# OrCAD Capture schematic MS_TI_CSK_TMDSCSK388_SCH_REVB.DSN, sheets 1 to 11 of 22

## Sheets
1 22.HARDWARE SCHEMATICS: title: HARDWARE SCHEMATICS; rev: B; note: MS_TI_CSK_TMDSCSK388_SCH_REVB
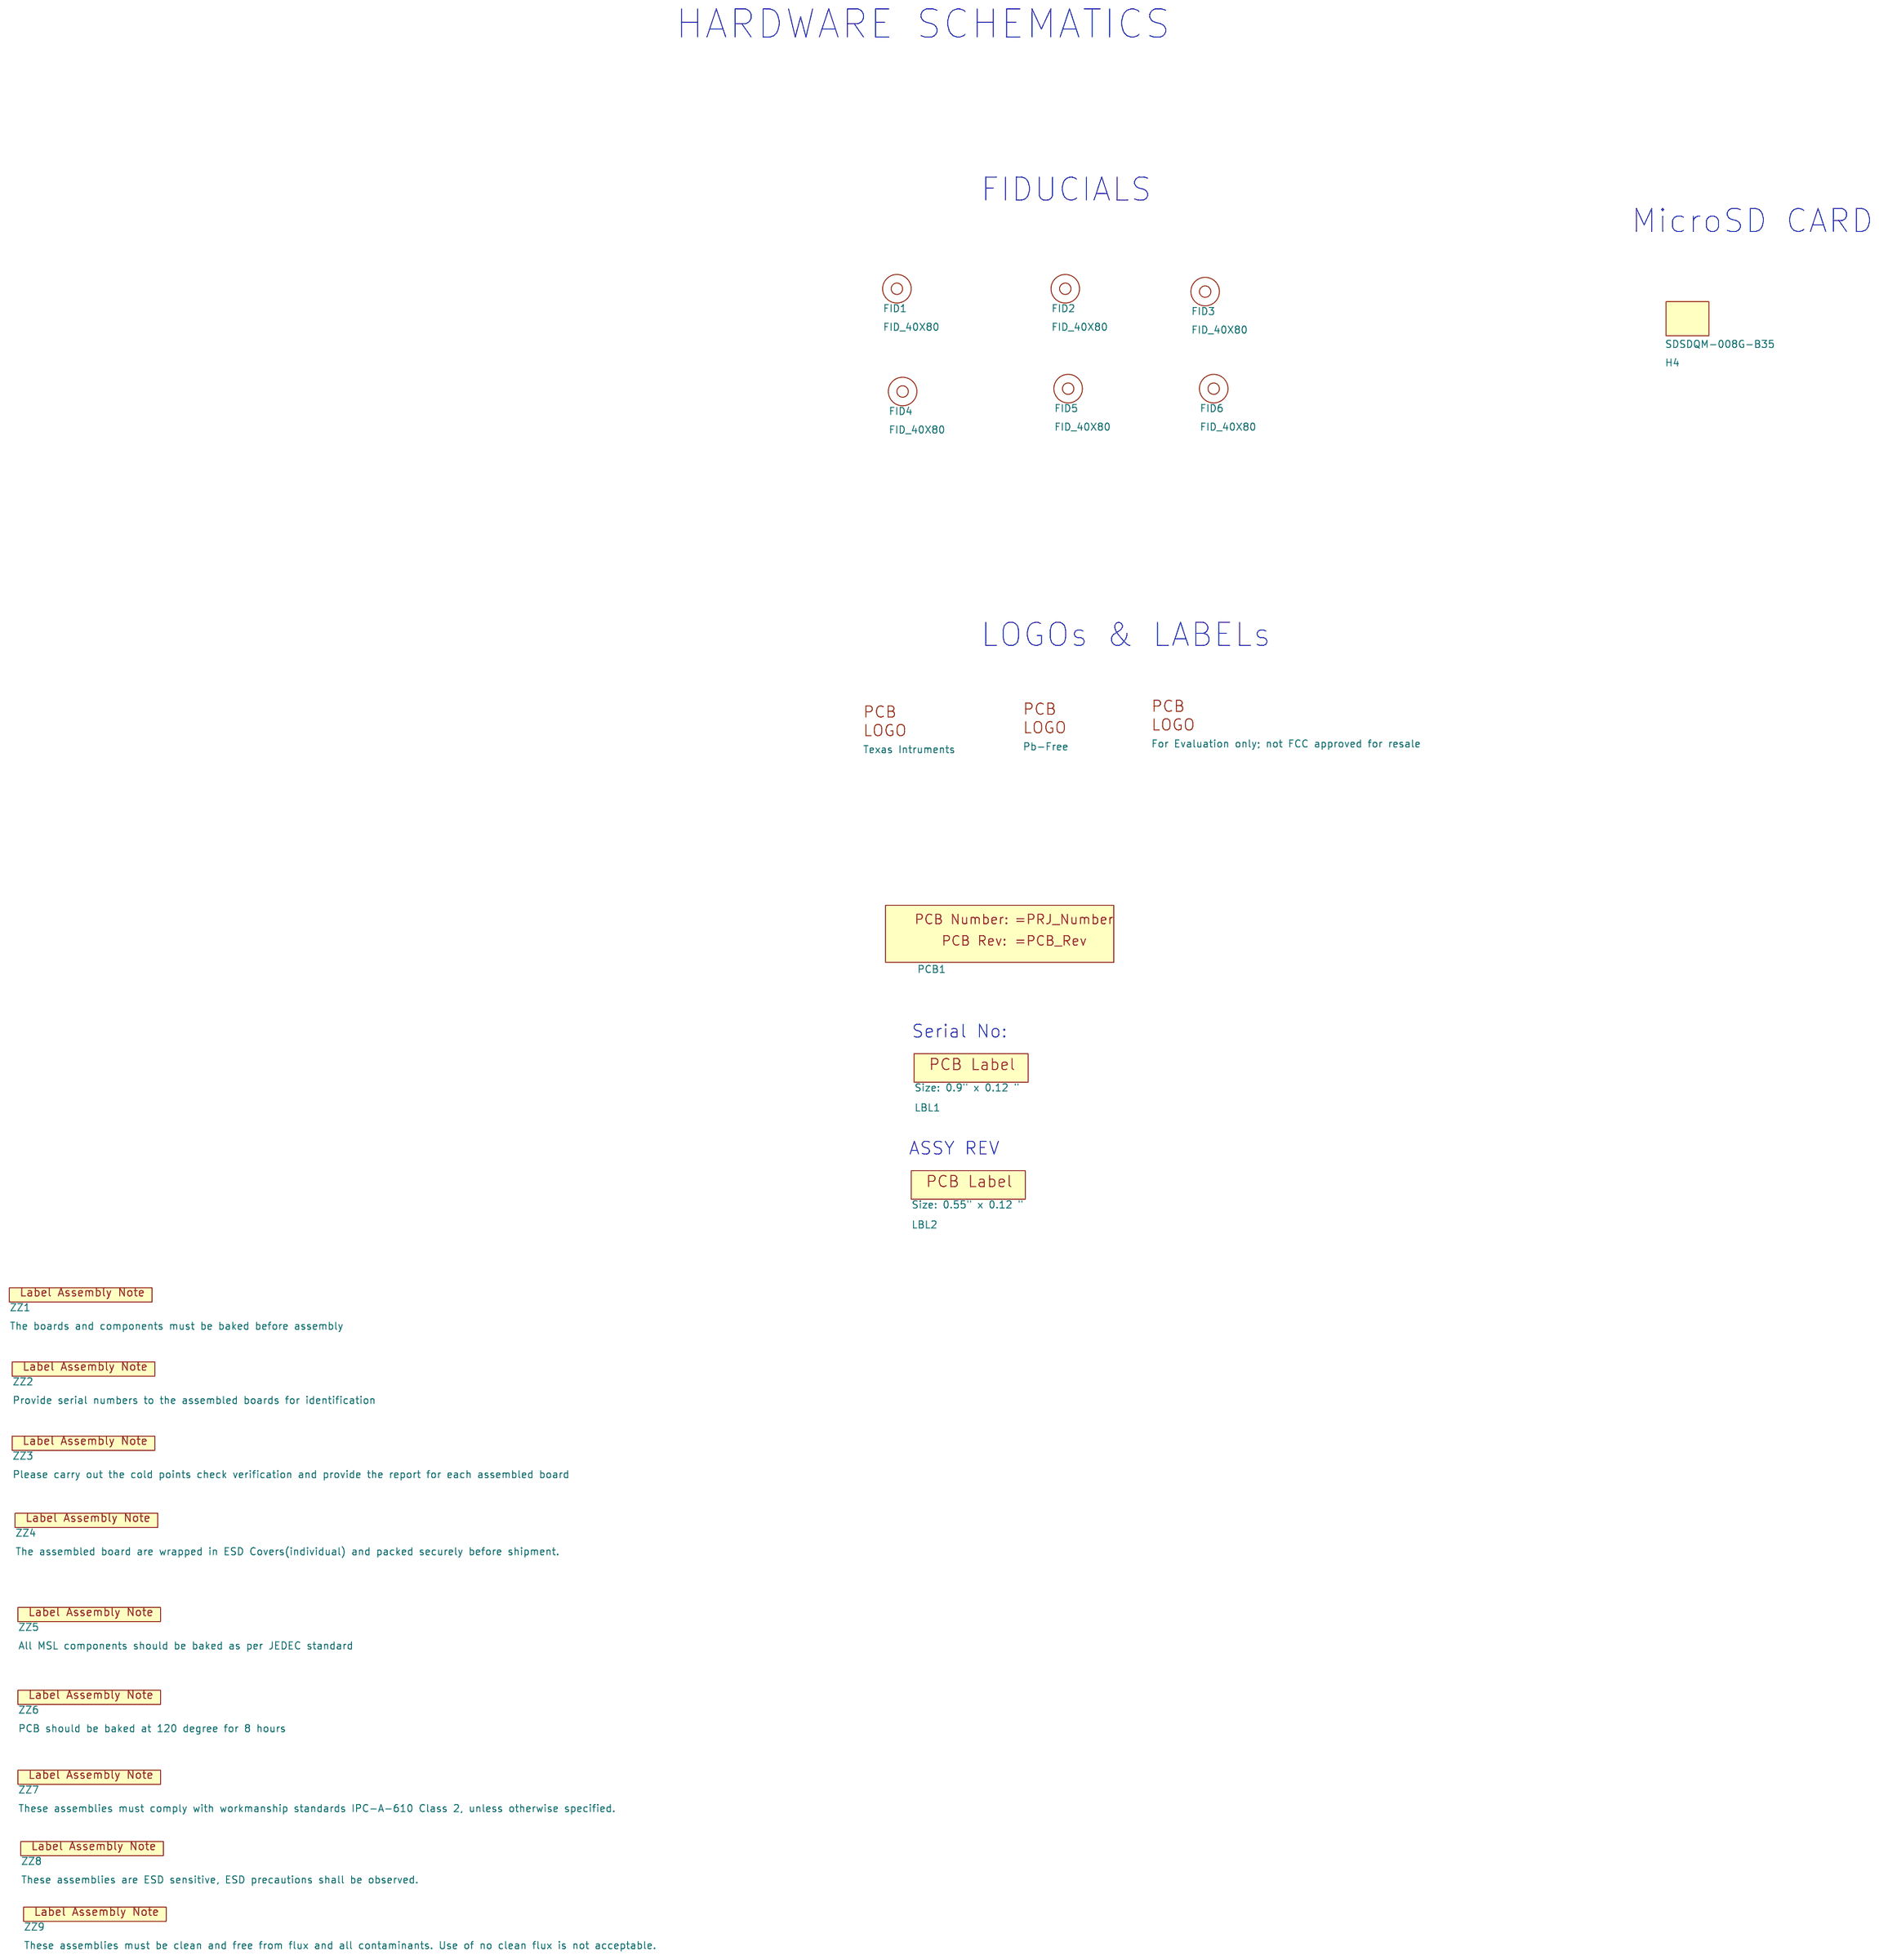
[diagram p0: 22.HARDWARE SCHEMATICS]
2 06.POWER CALCULATION: title: POWER CALCULATION
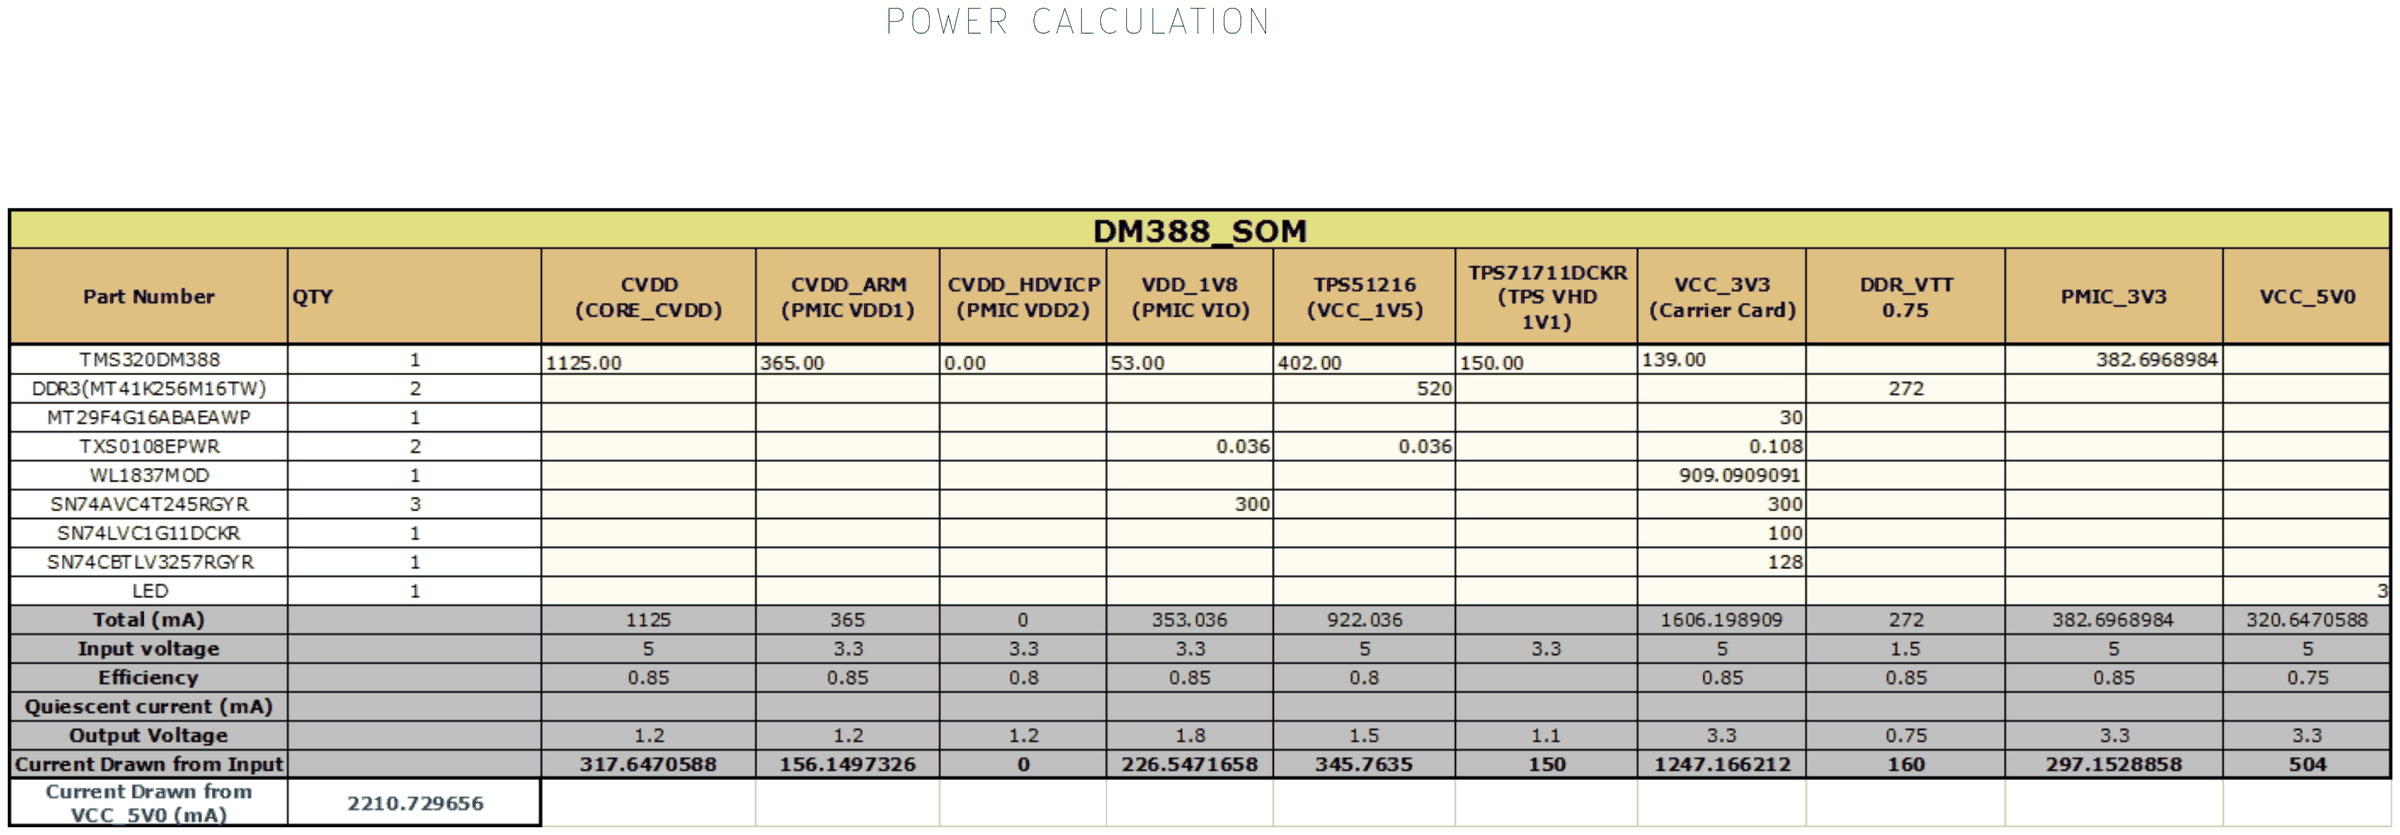
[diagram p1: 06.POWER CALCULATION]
3 05.POWER UP SEQUENCE: title: POWER UP SEQUENCE
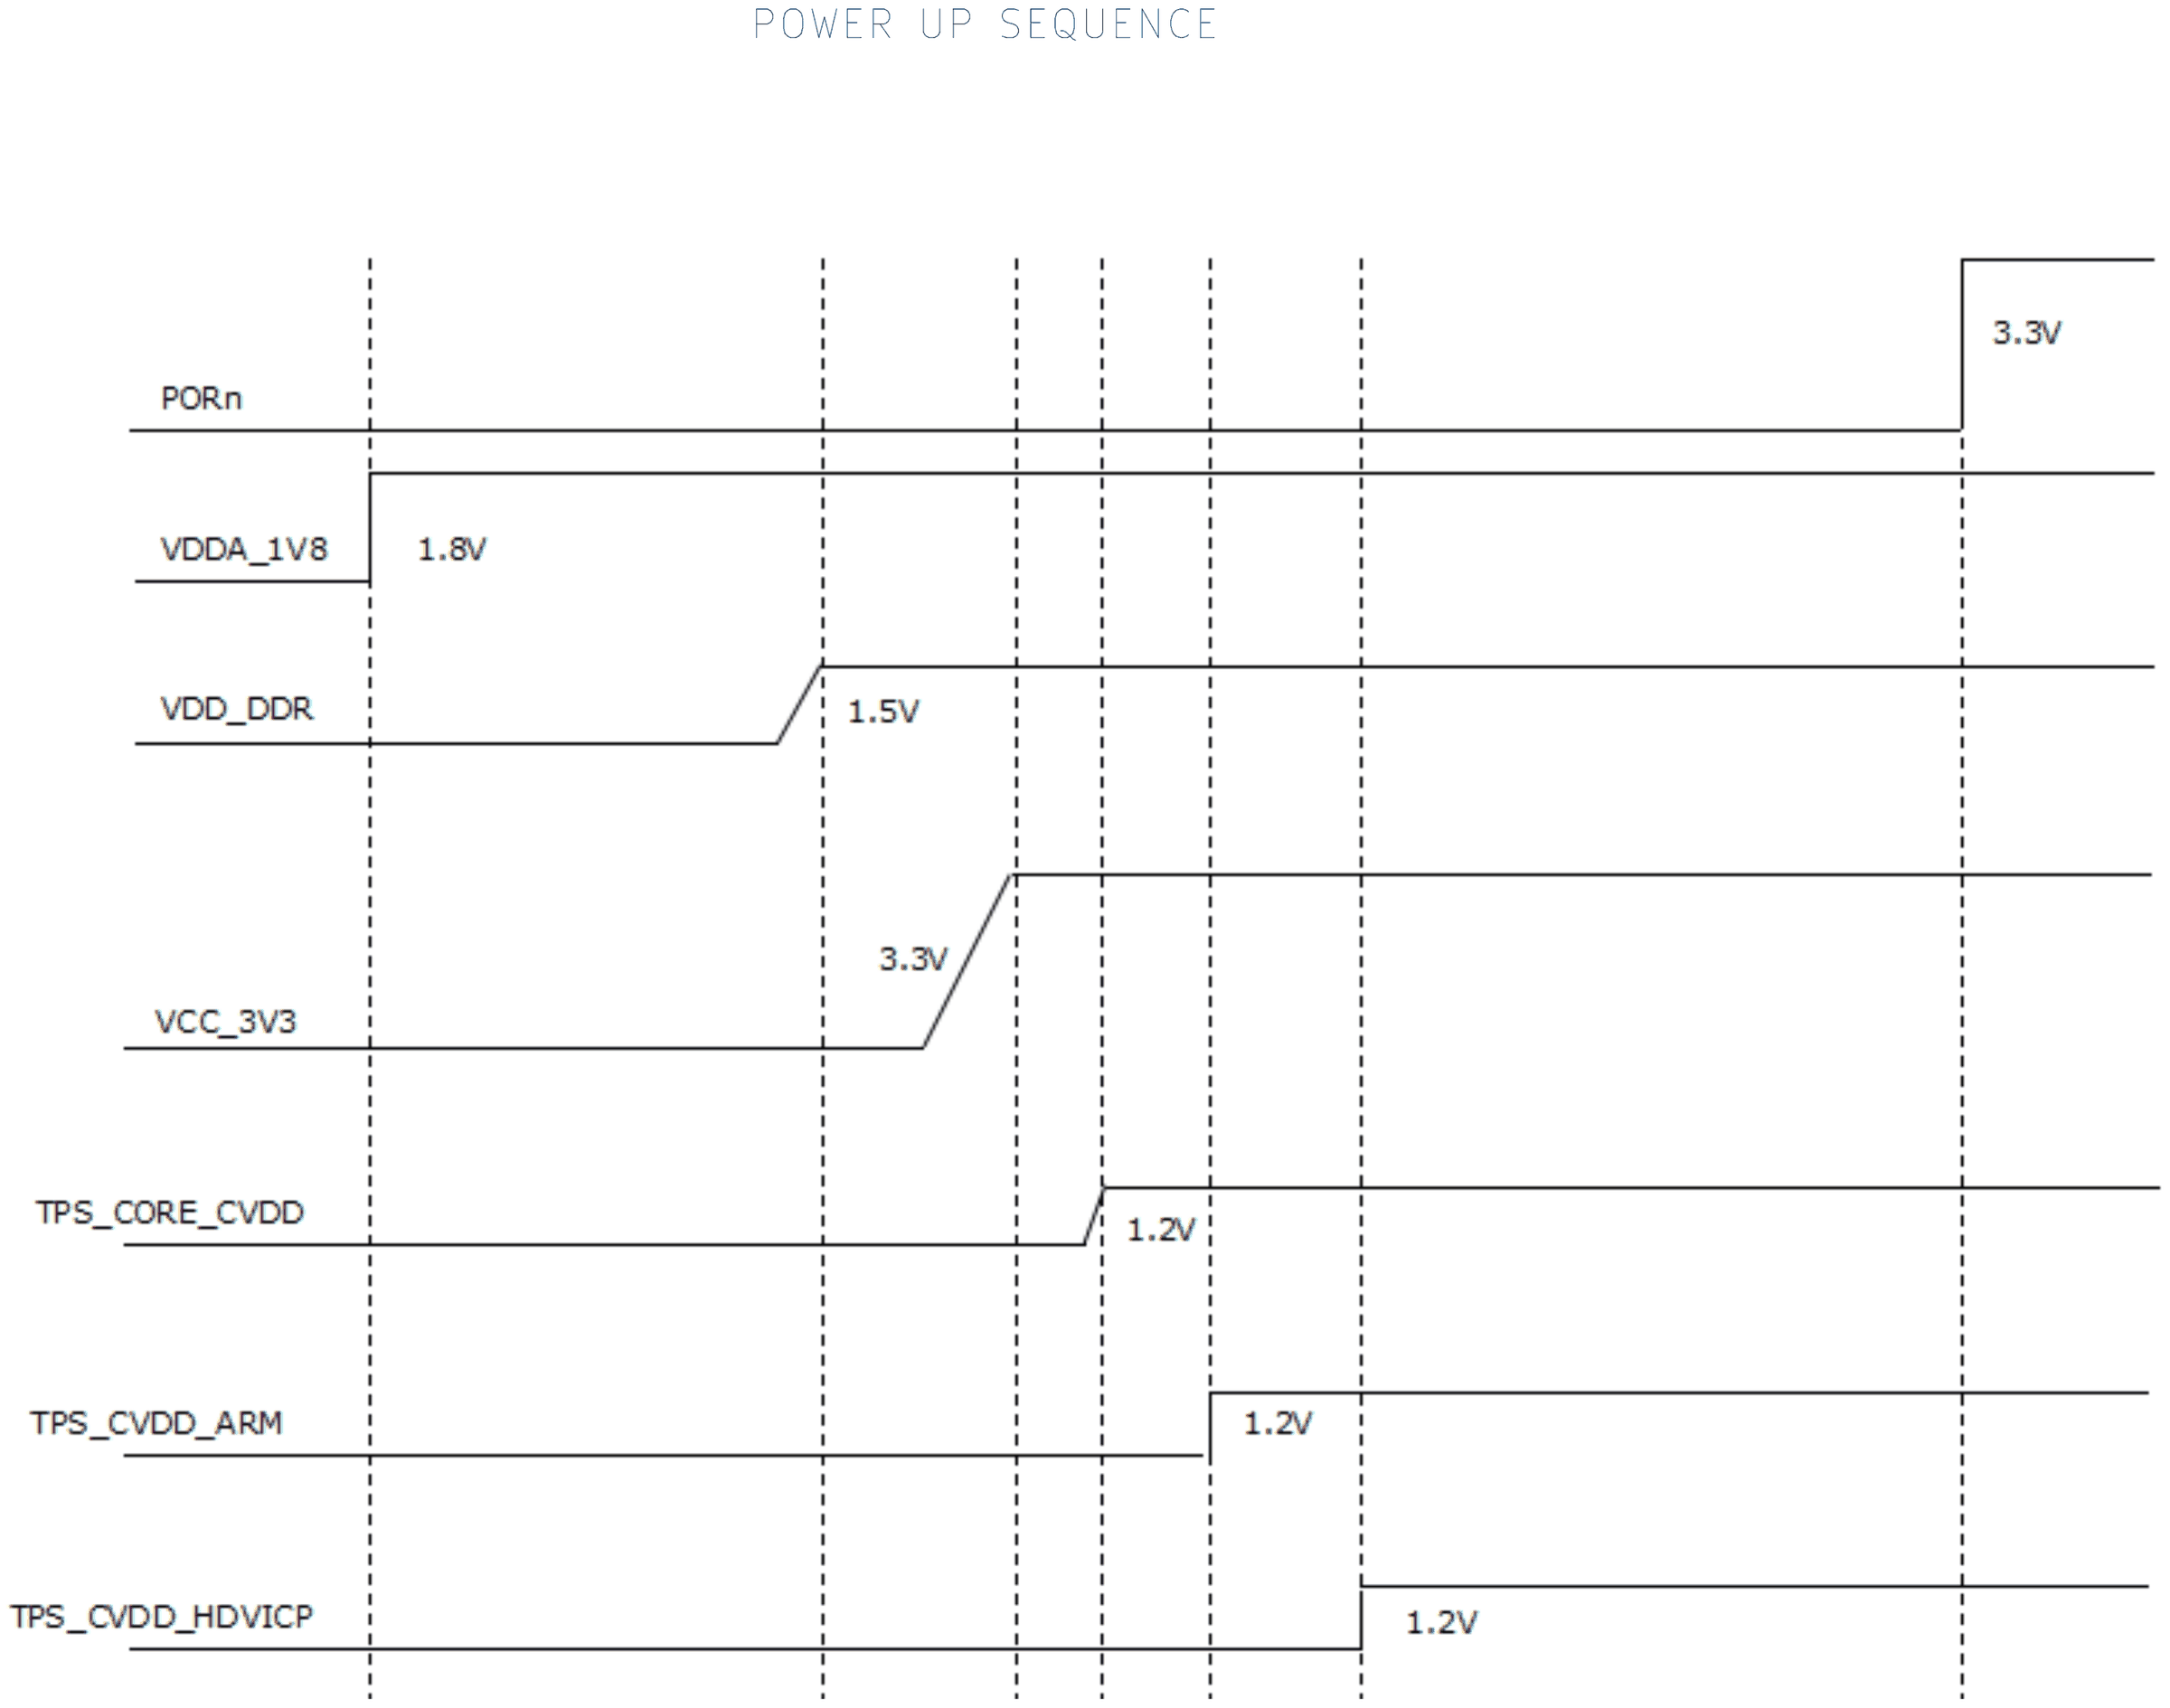
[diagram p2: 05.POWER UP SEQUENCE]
4 07.GPIO & I2C ADDRESS TABLE: title: GPIO & I2C ADDRESS TABLE
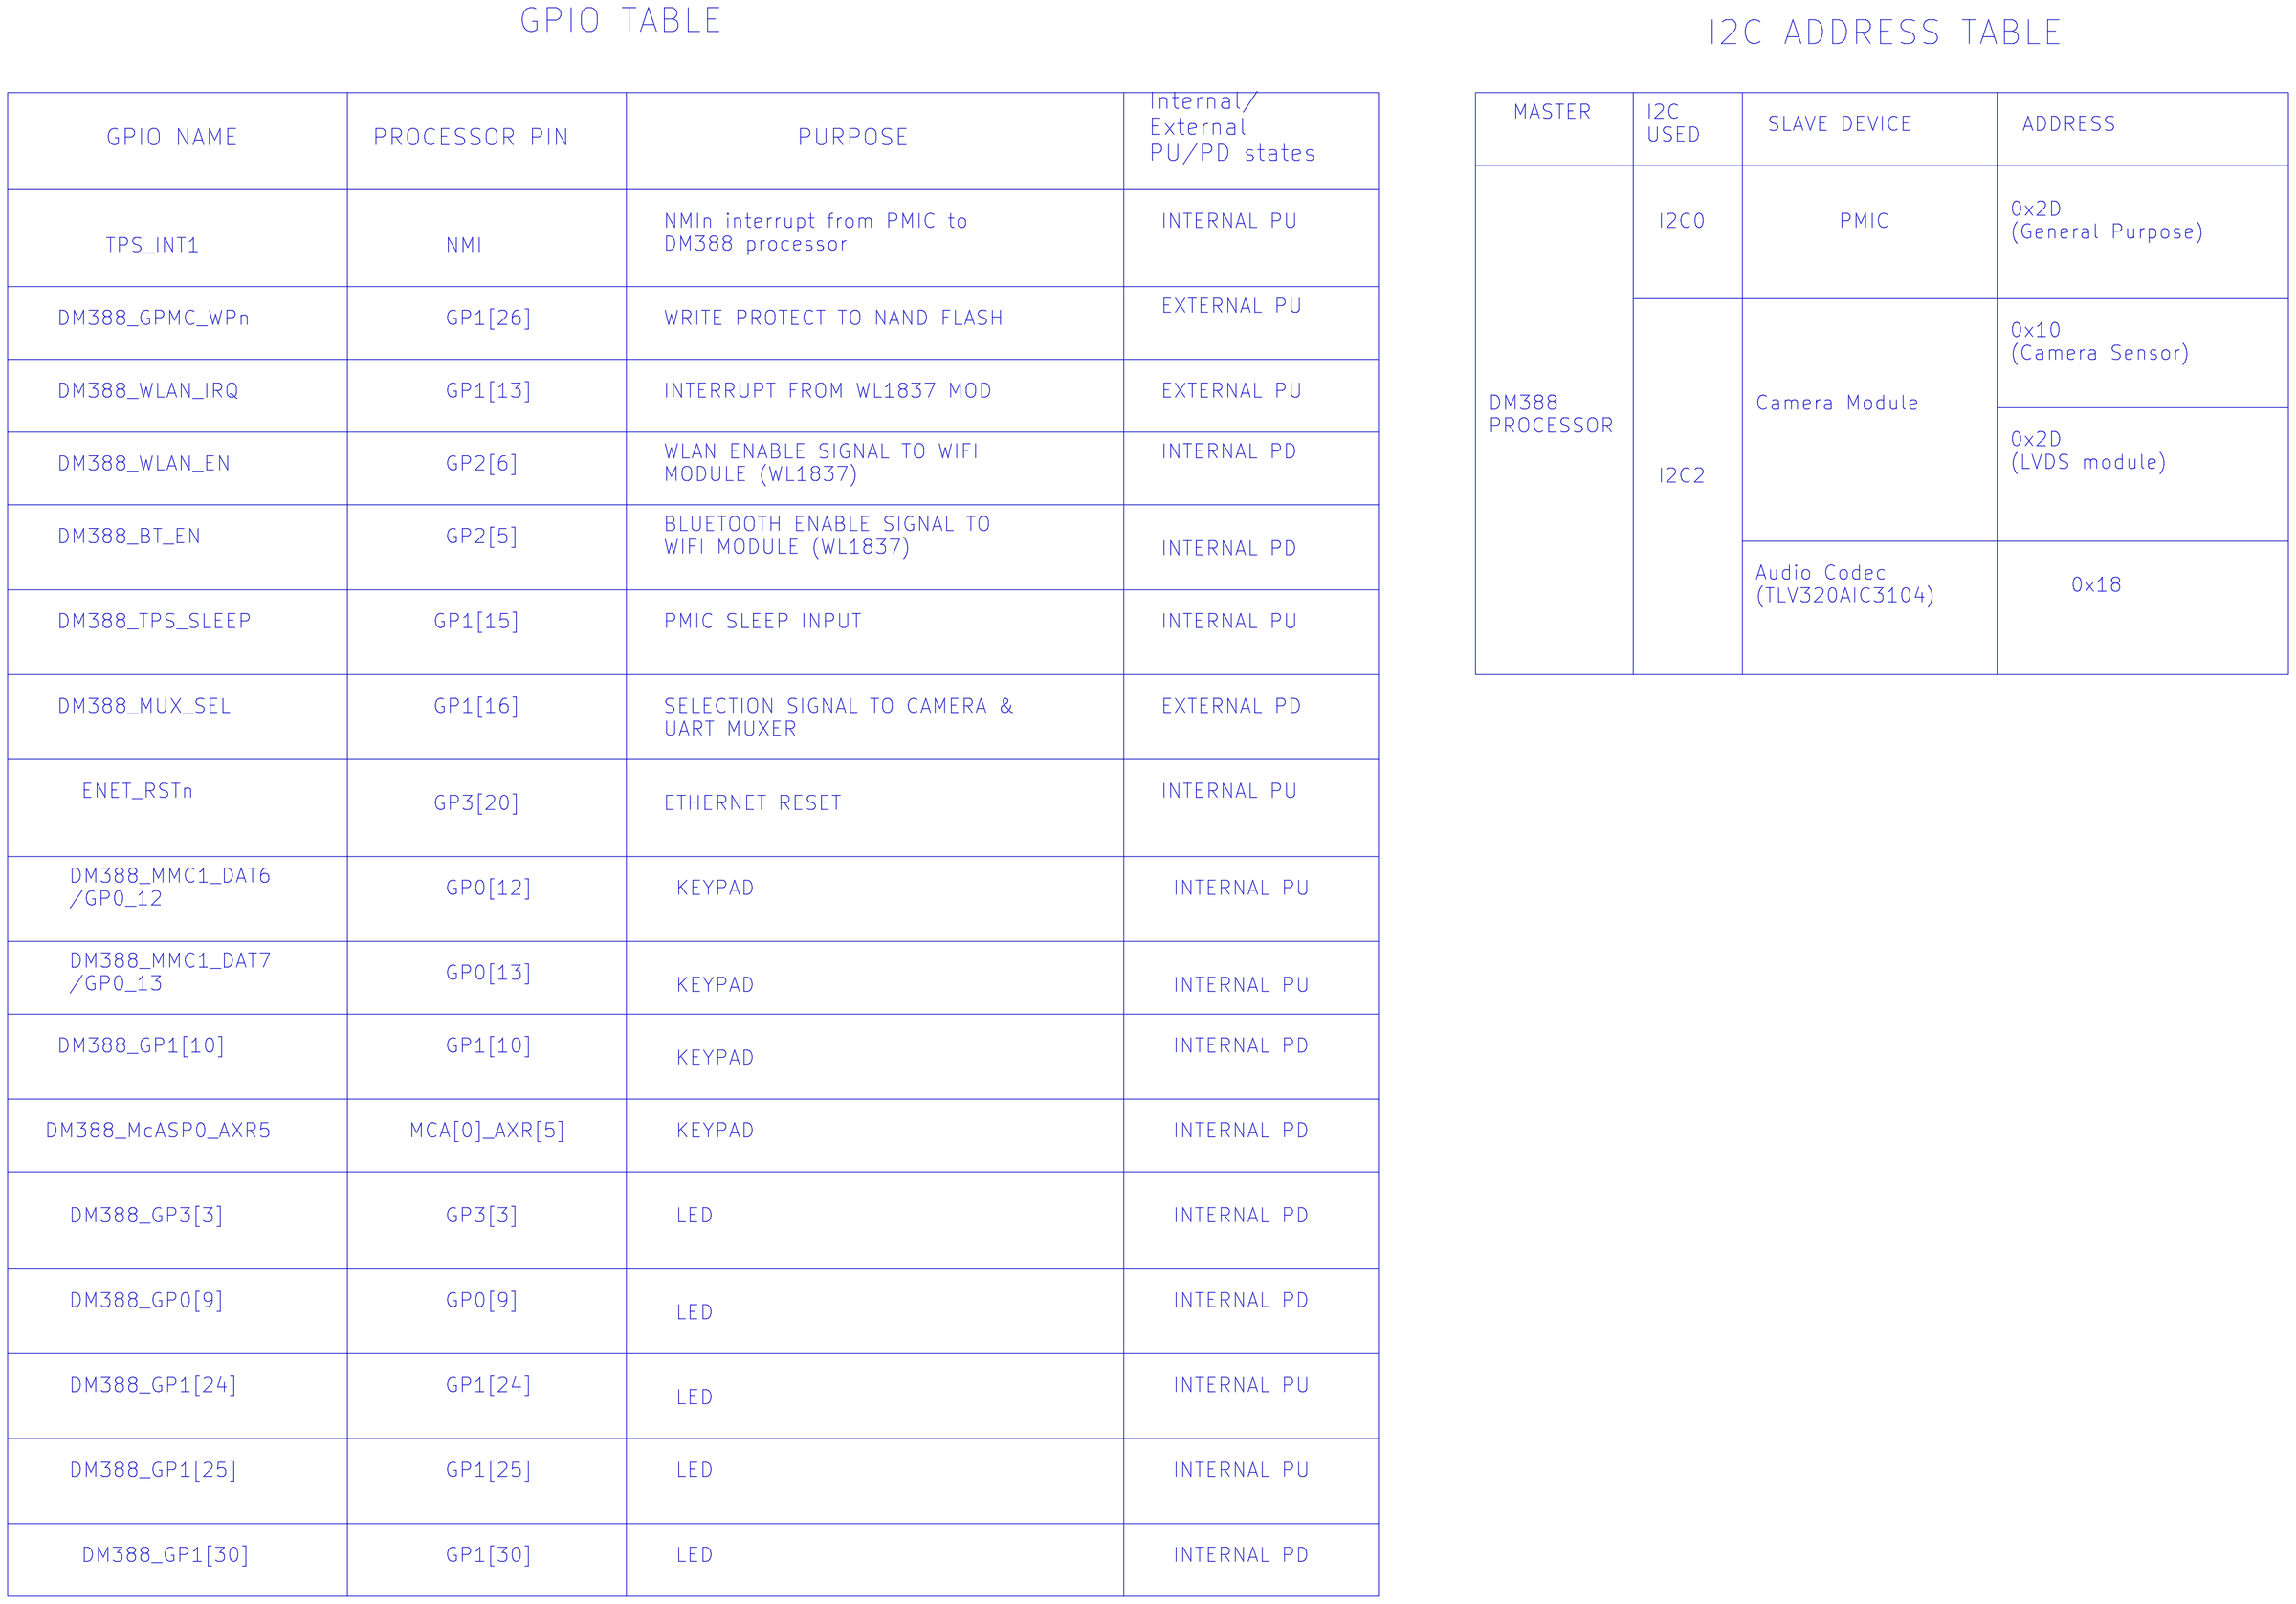
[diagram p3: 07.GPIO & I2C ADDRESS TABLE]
5 01.TABLE OF CONTENTS: title: TABLE OF CONTENTS
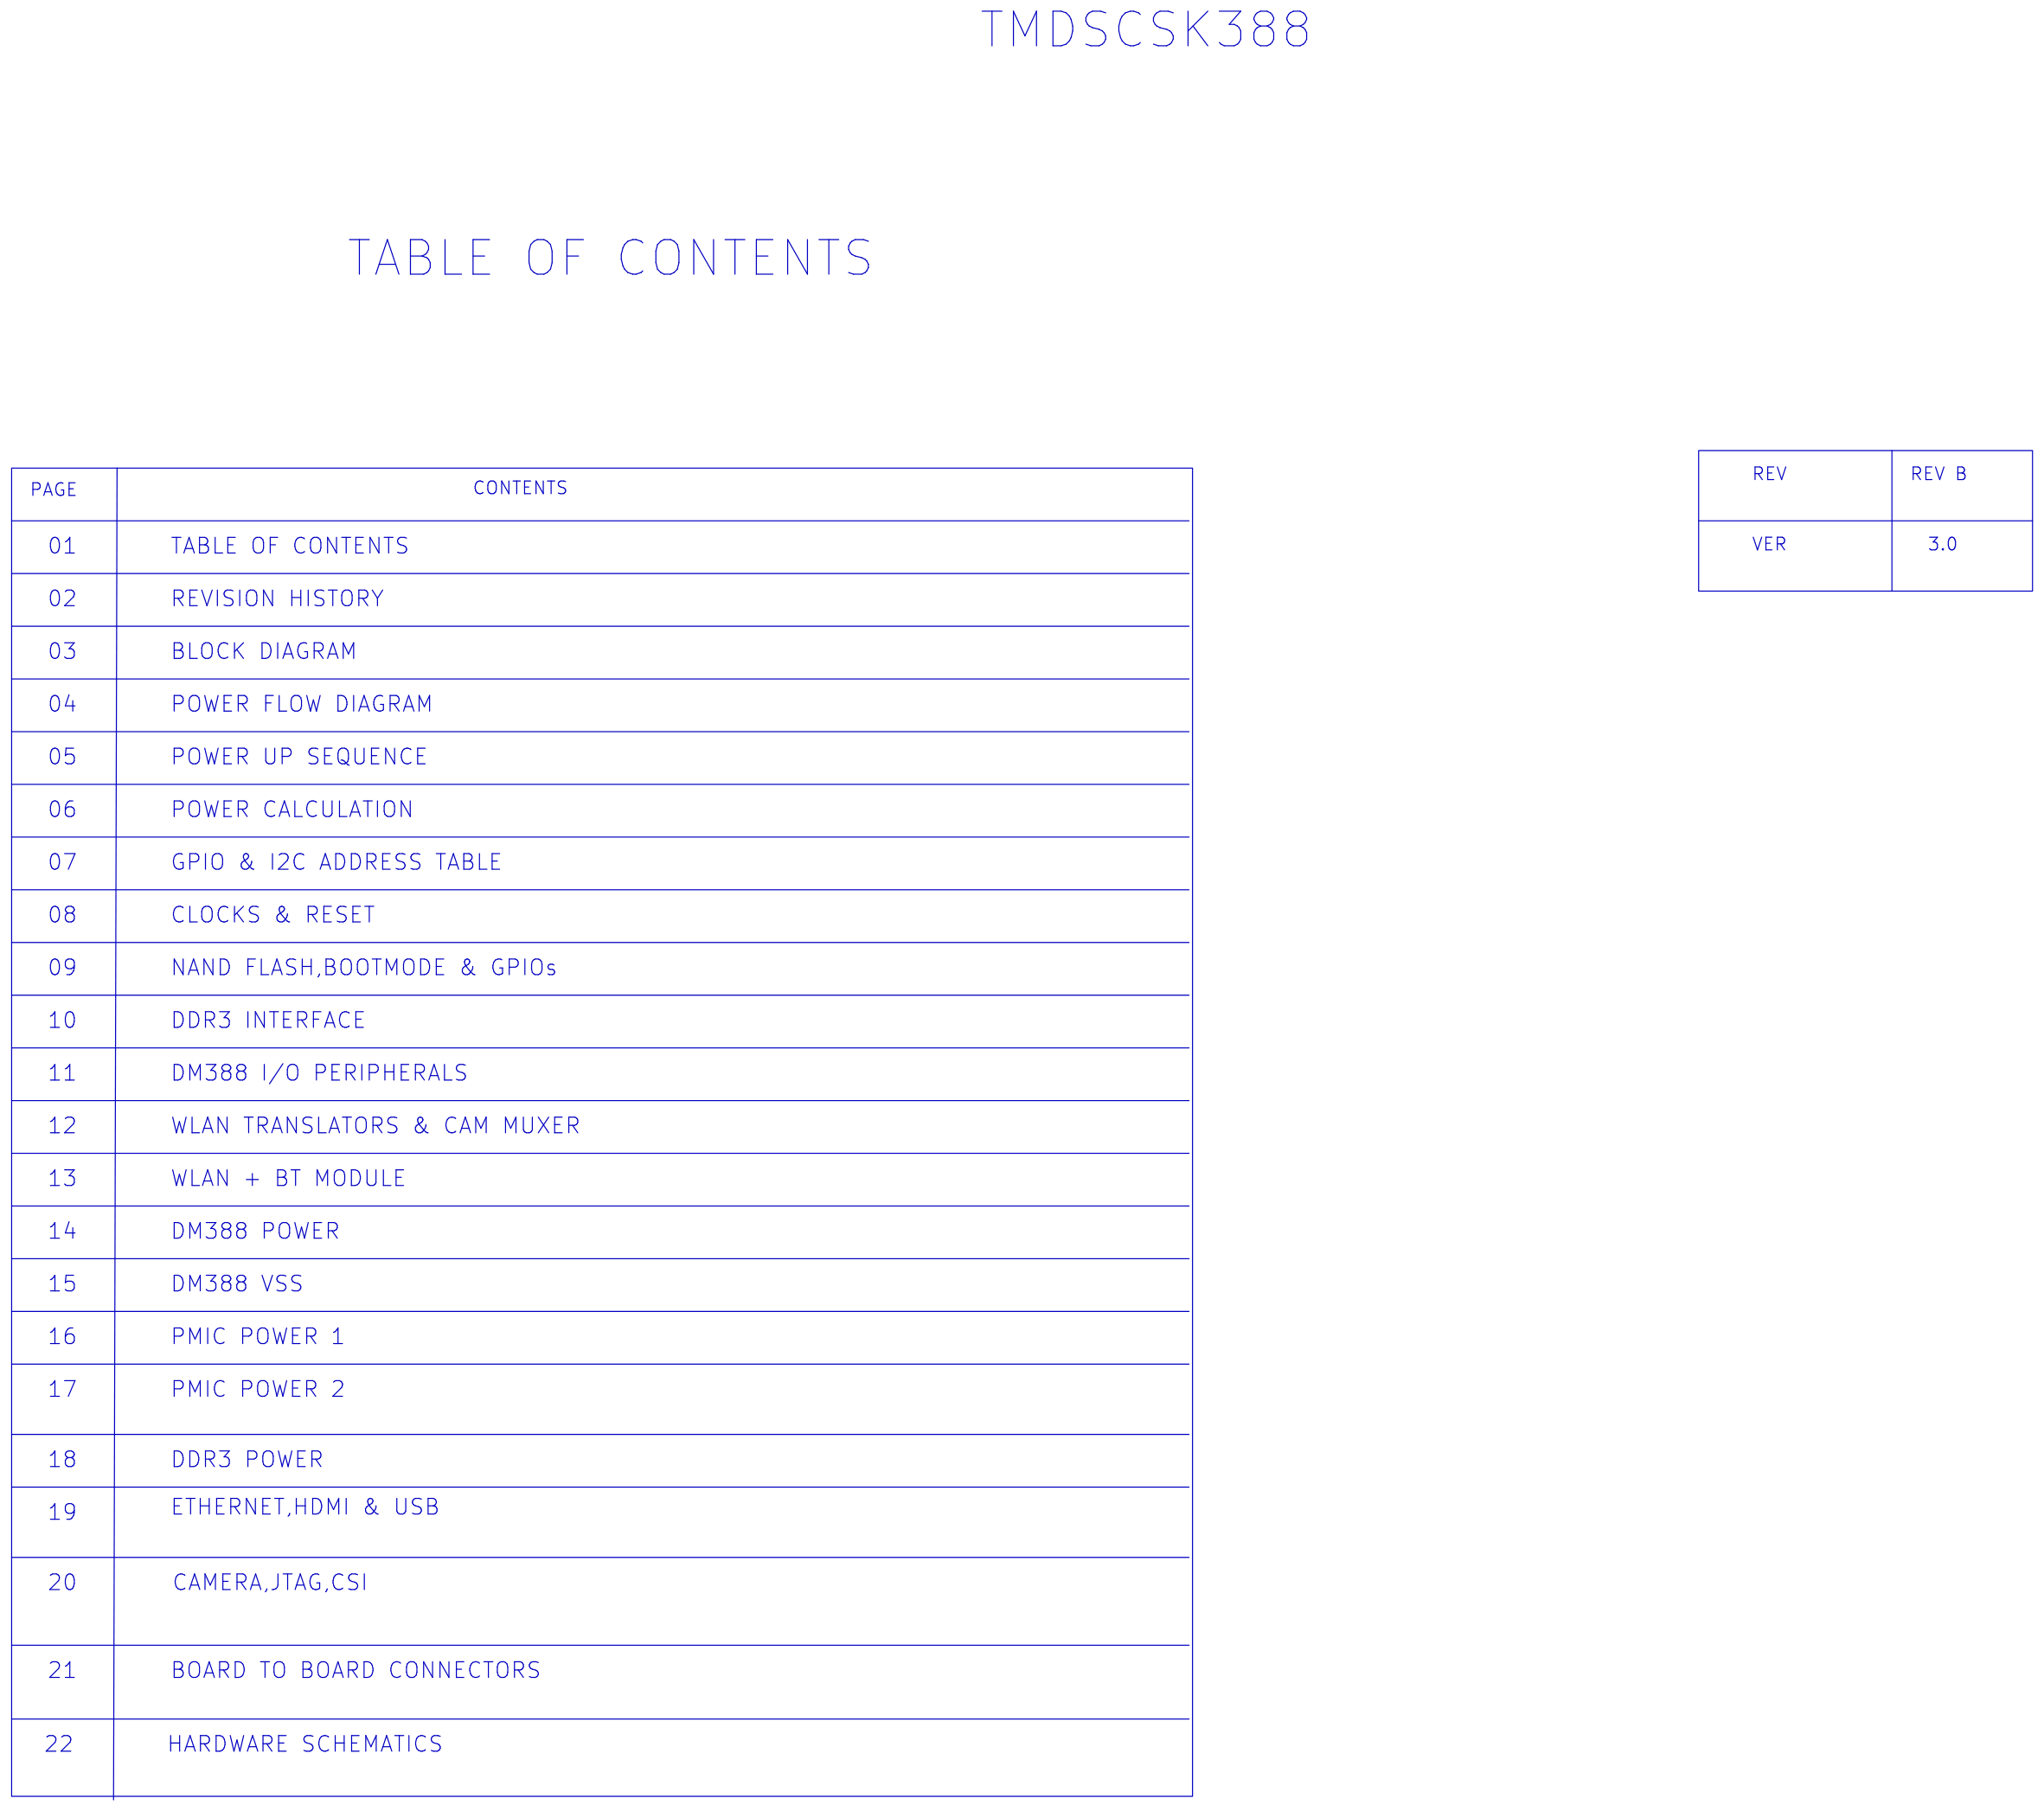
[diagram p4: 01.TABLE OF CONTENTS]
6 02. REVISION HISTORY: title: REVISION HISTORY
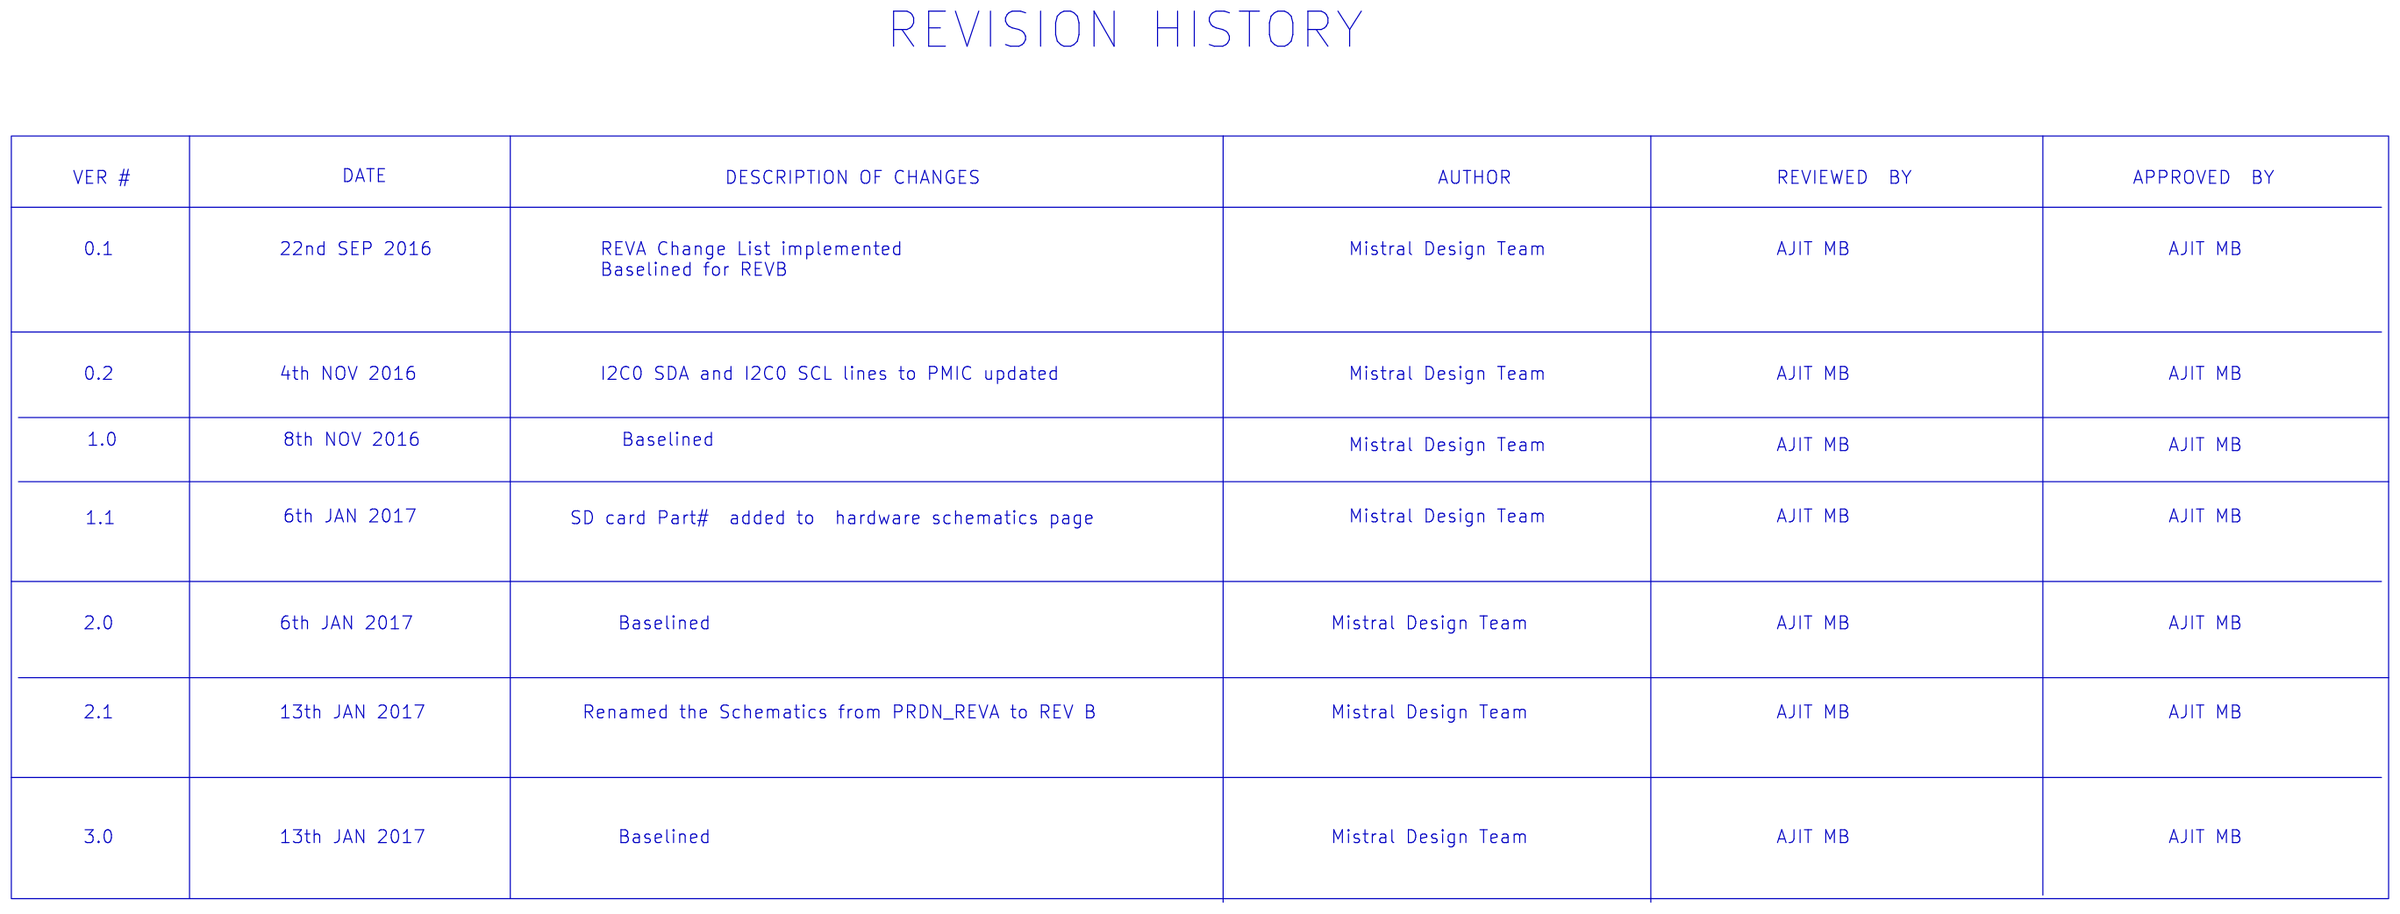
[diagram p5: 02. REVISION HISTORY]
7 03. BLOCK DIAGRAM: title: BLOCK DIAGRAM
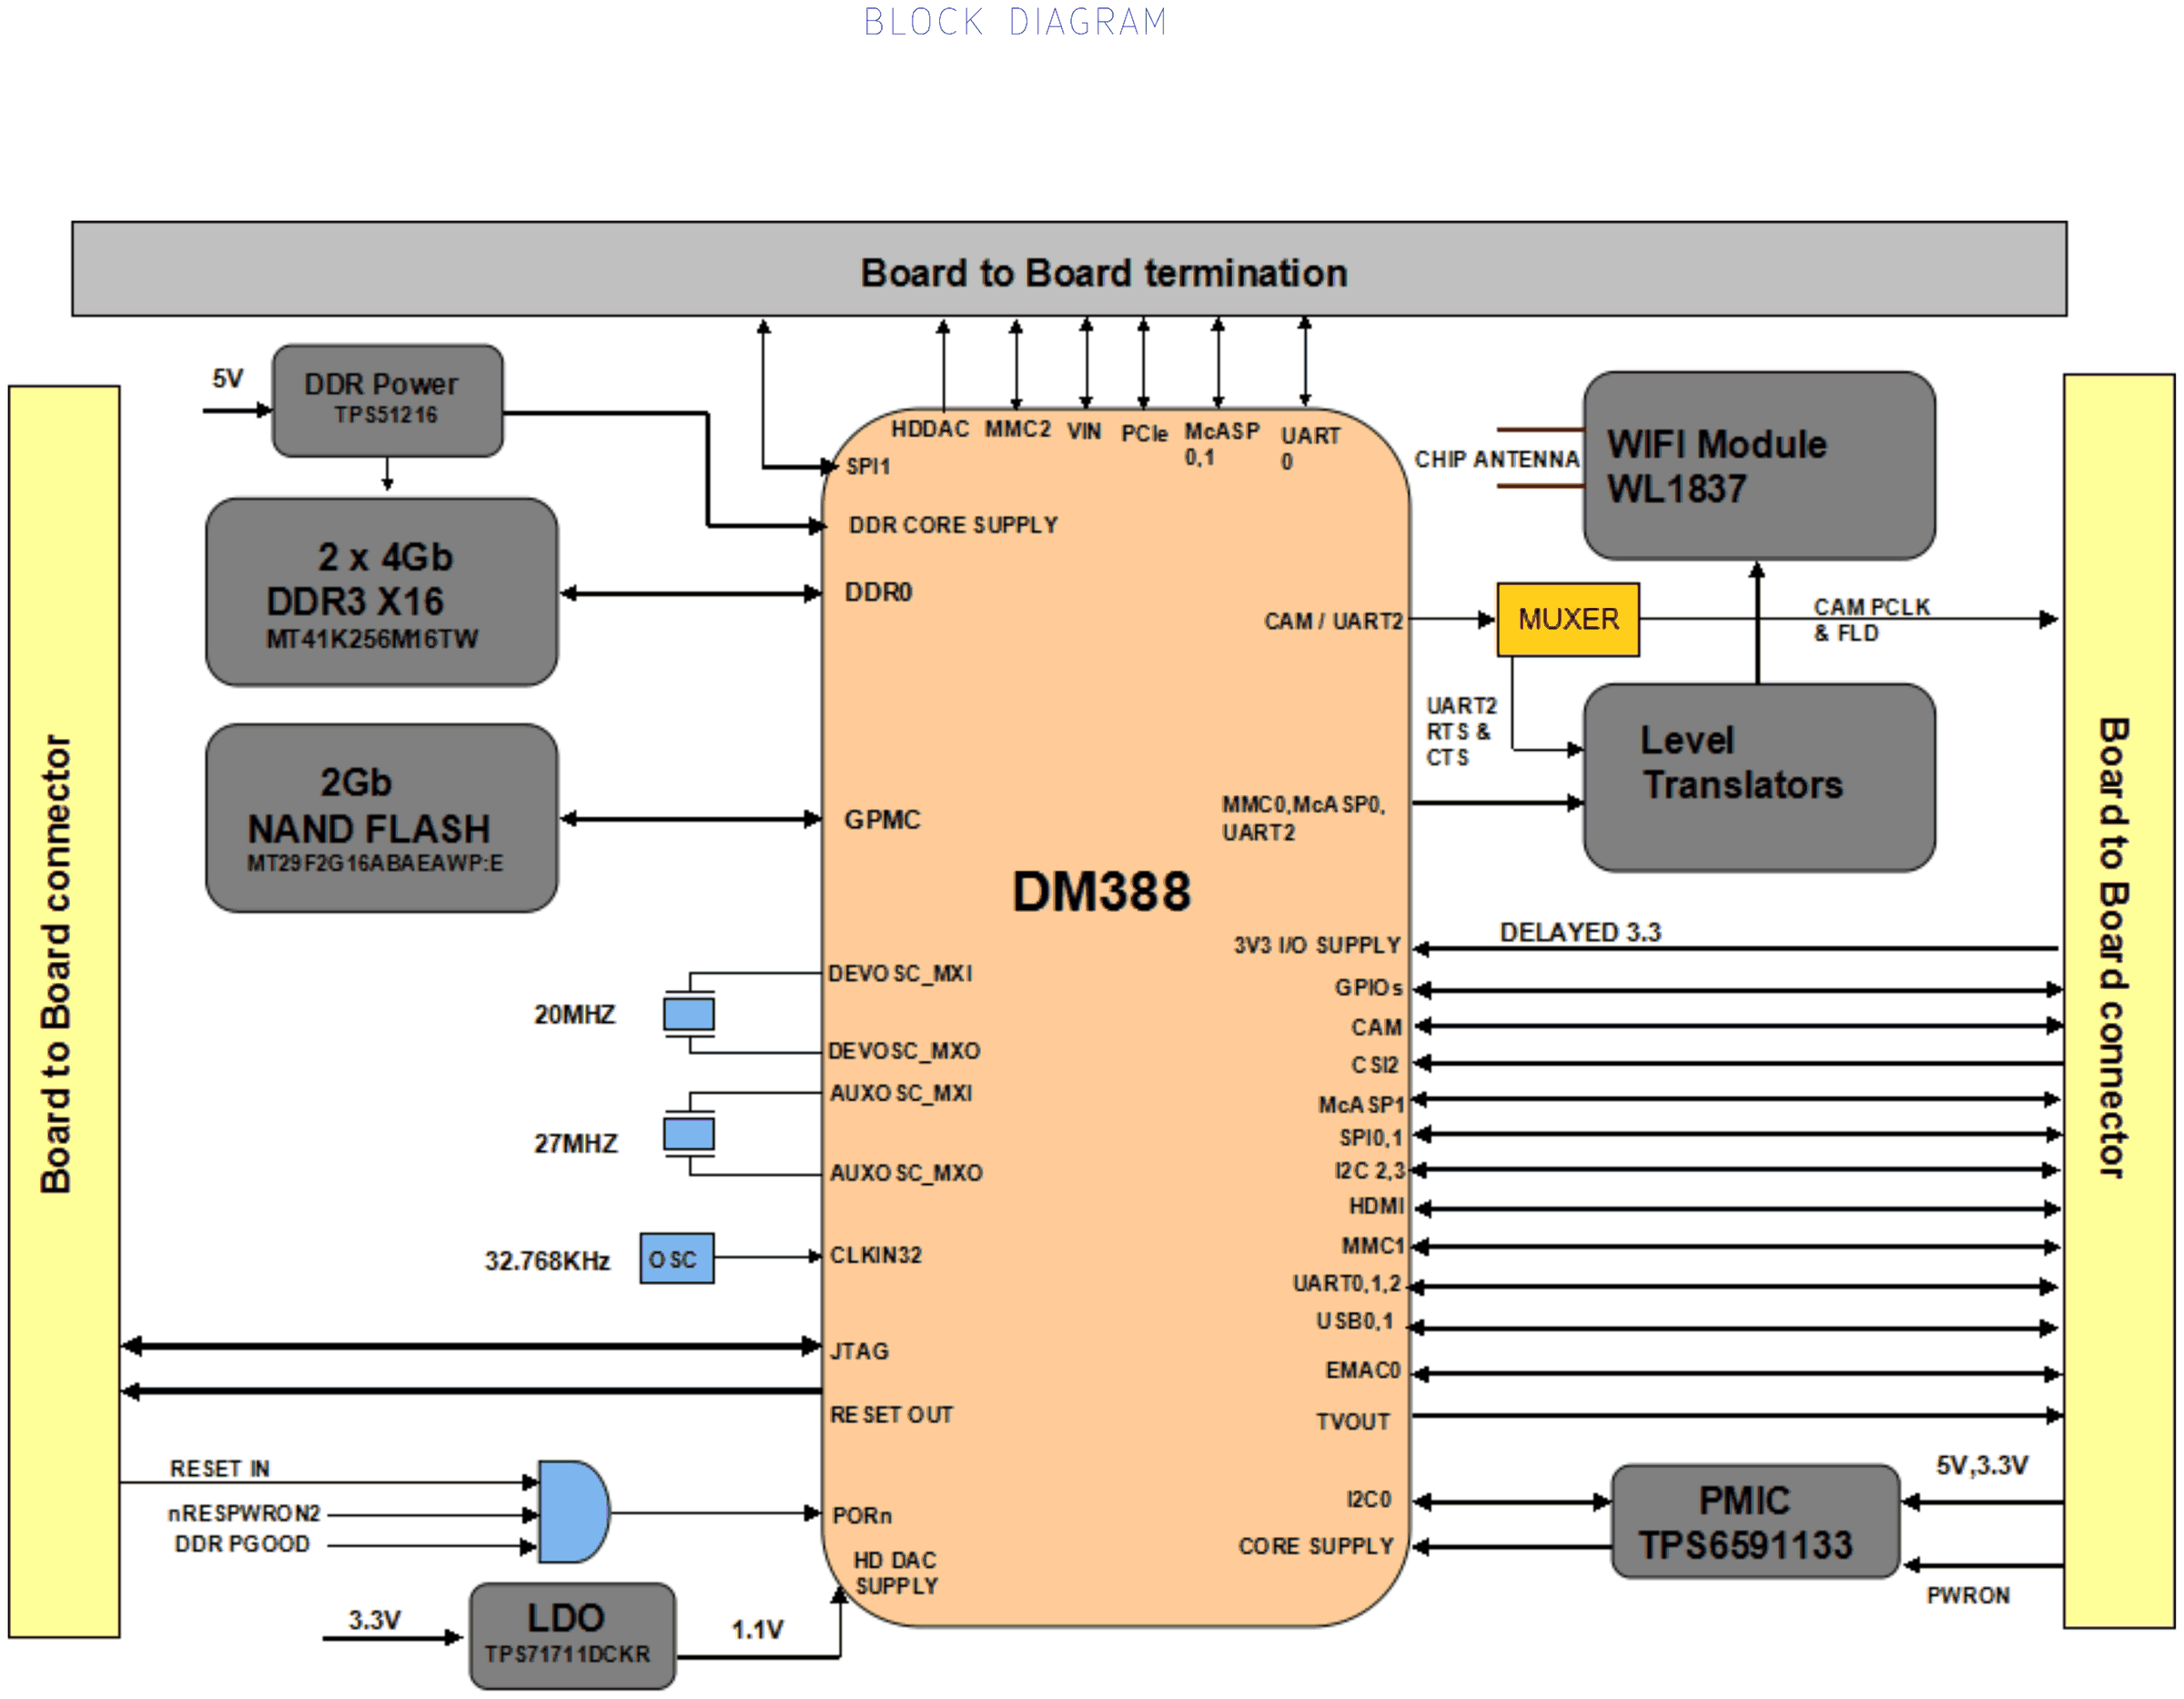
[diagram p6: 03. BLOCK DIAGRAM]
8 04.POWER FLOW DIAGRAM: title: POWER FLOW DIAGRAM
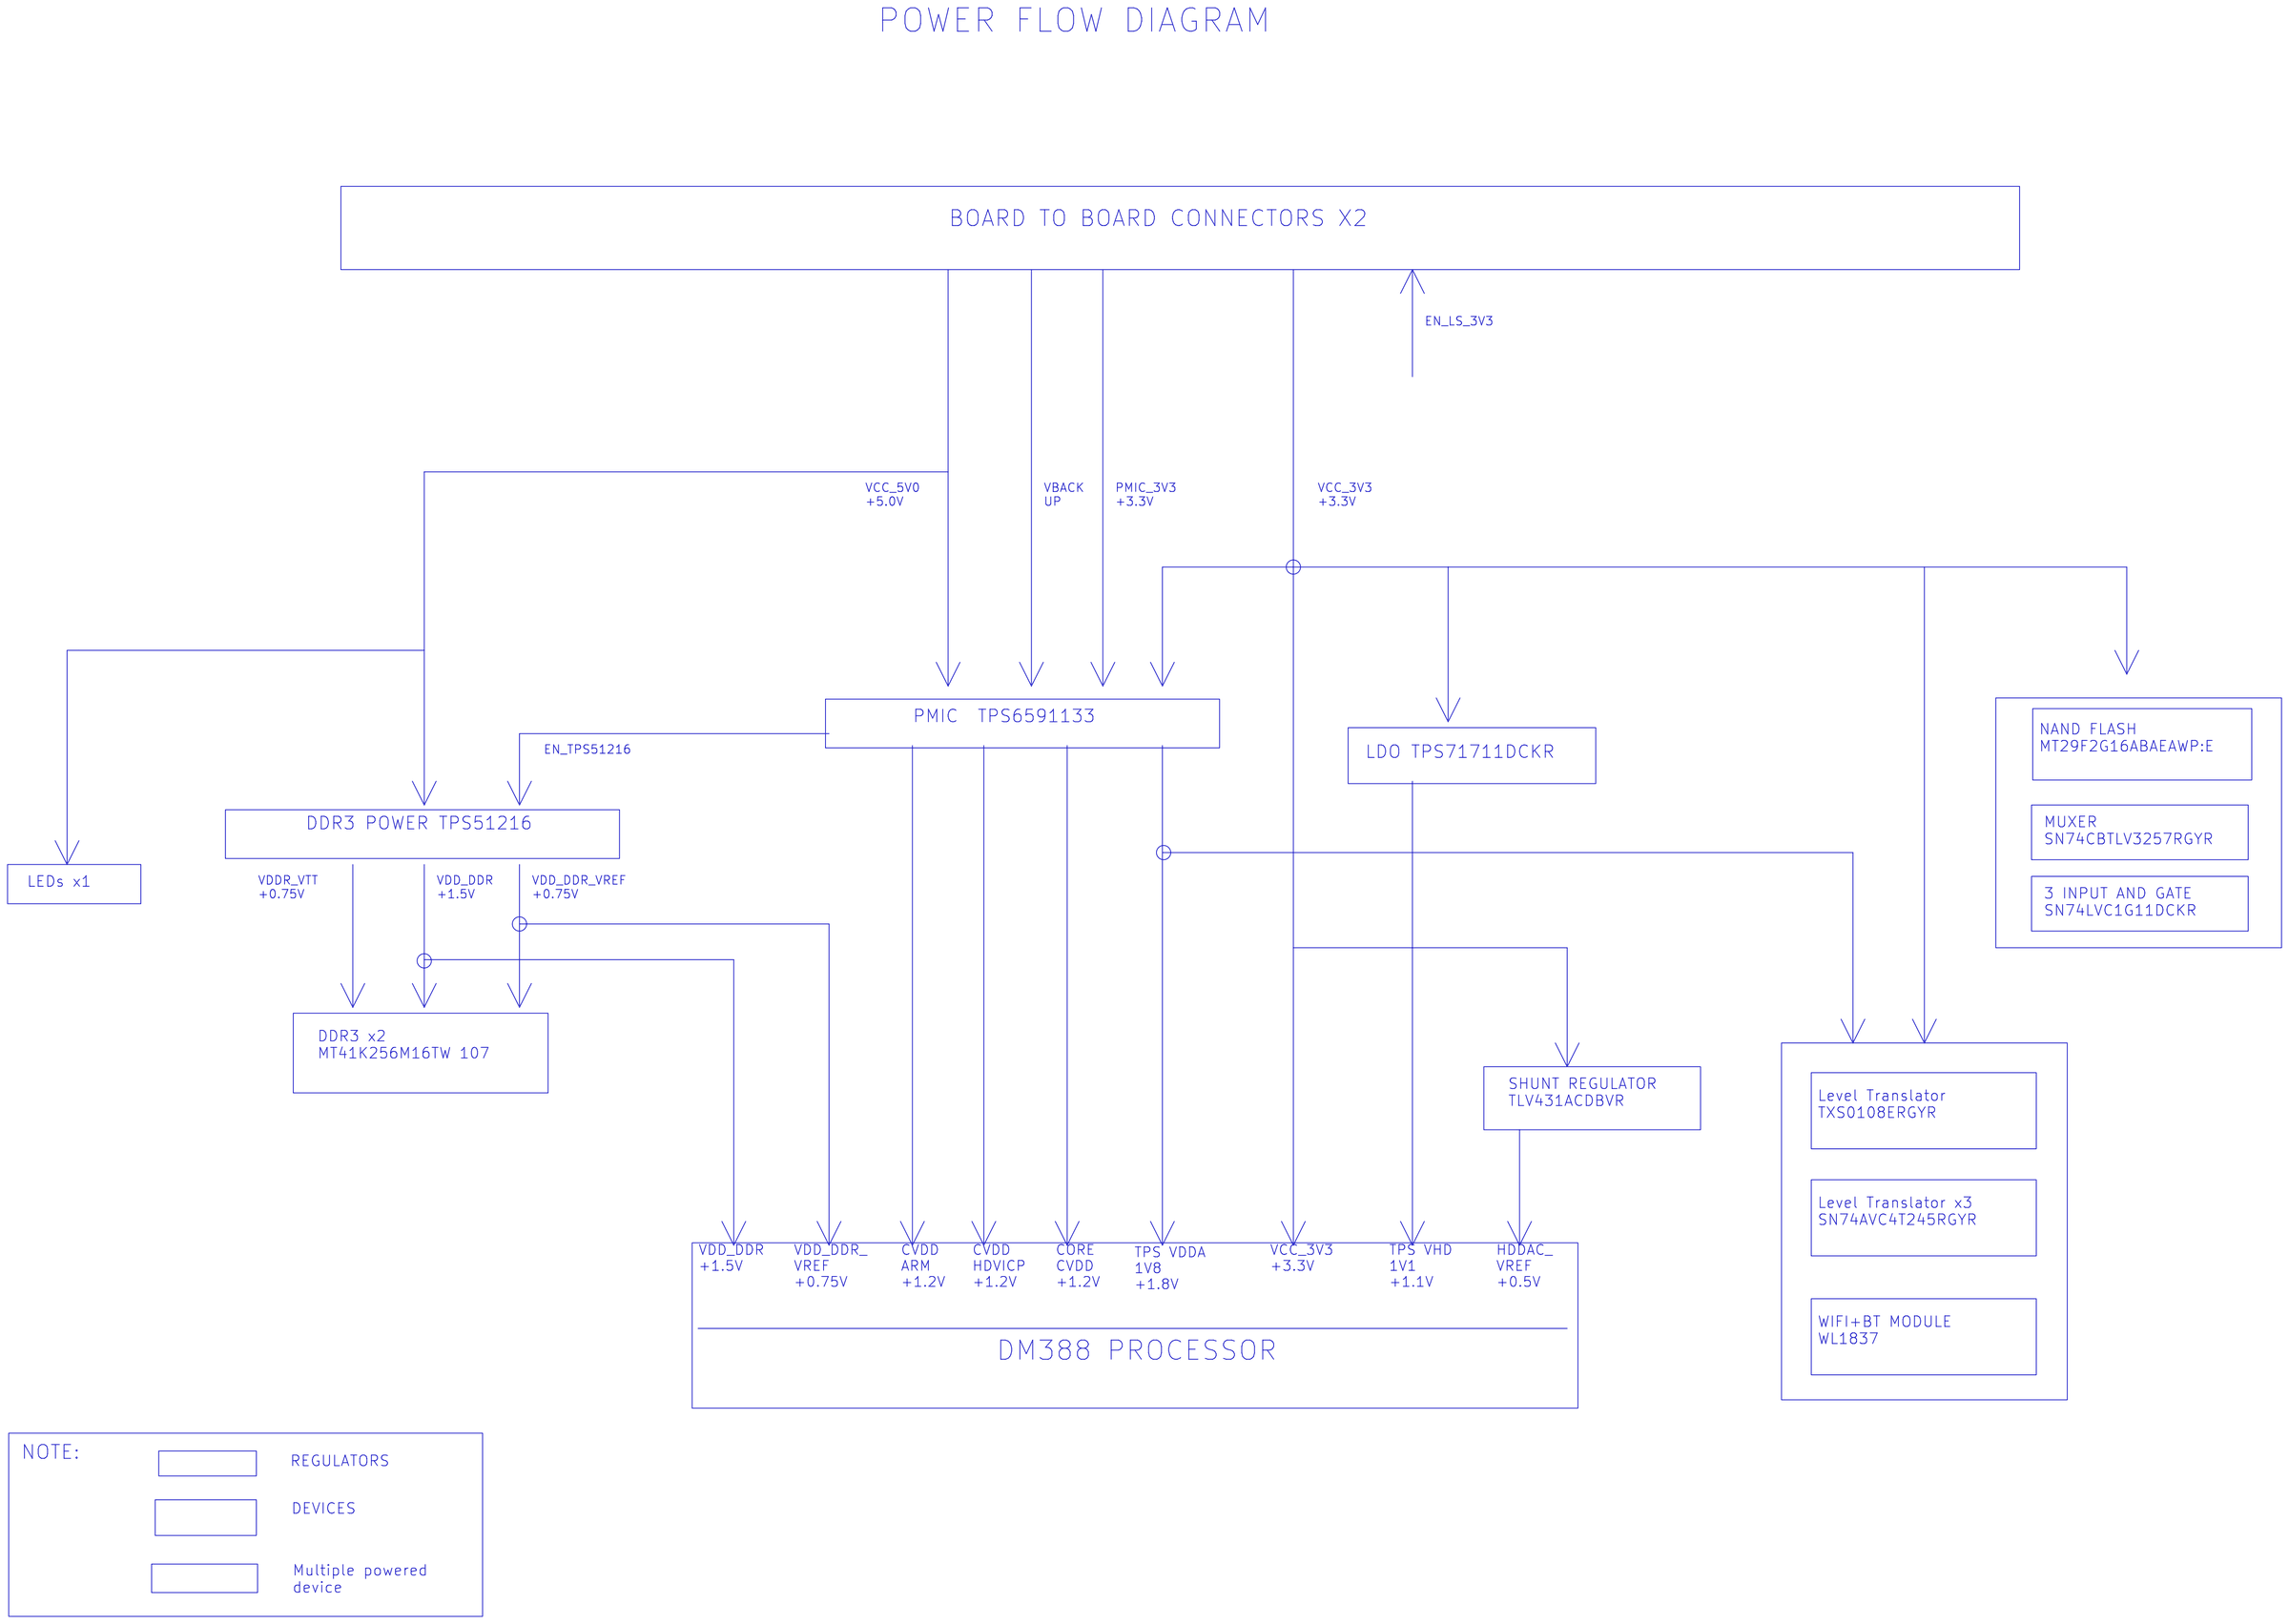
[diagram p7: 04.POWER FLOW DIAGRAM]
9 08.CLOCKS & RESET: size C; title: CLOCKS AND RESET
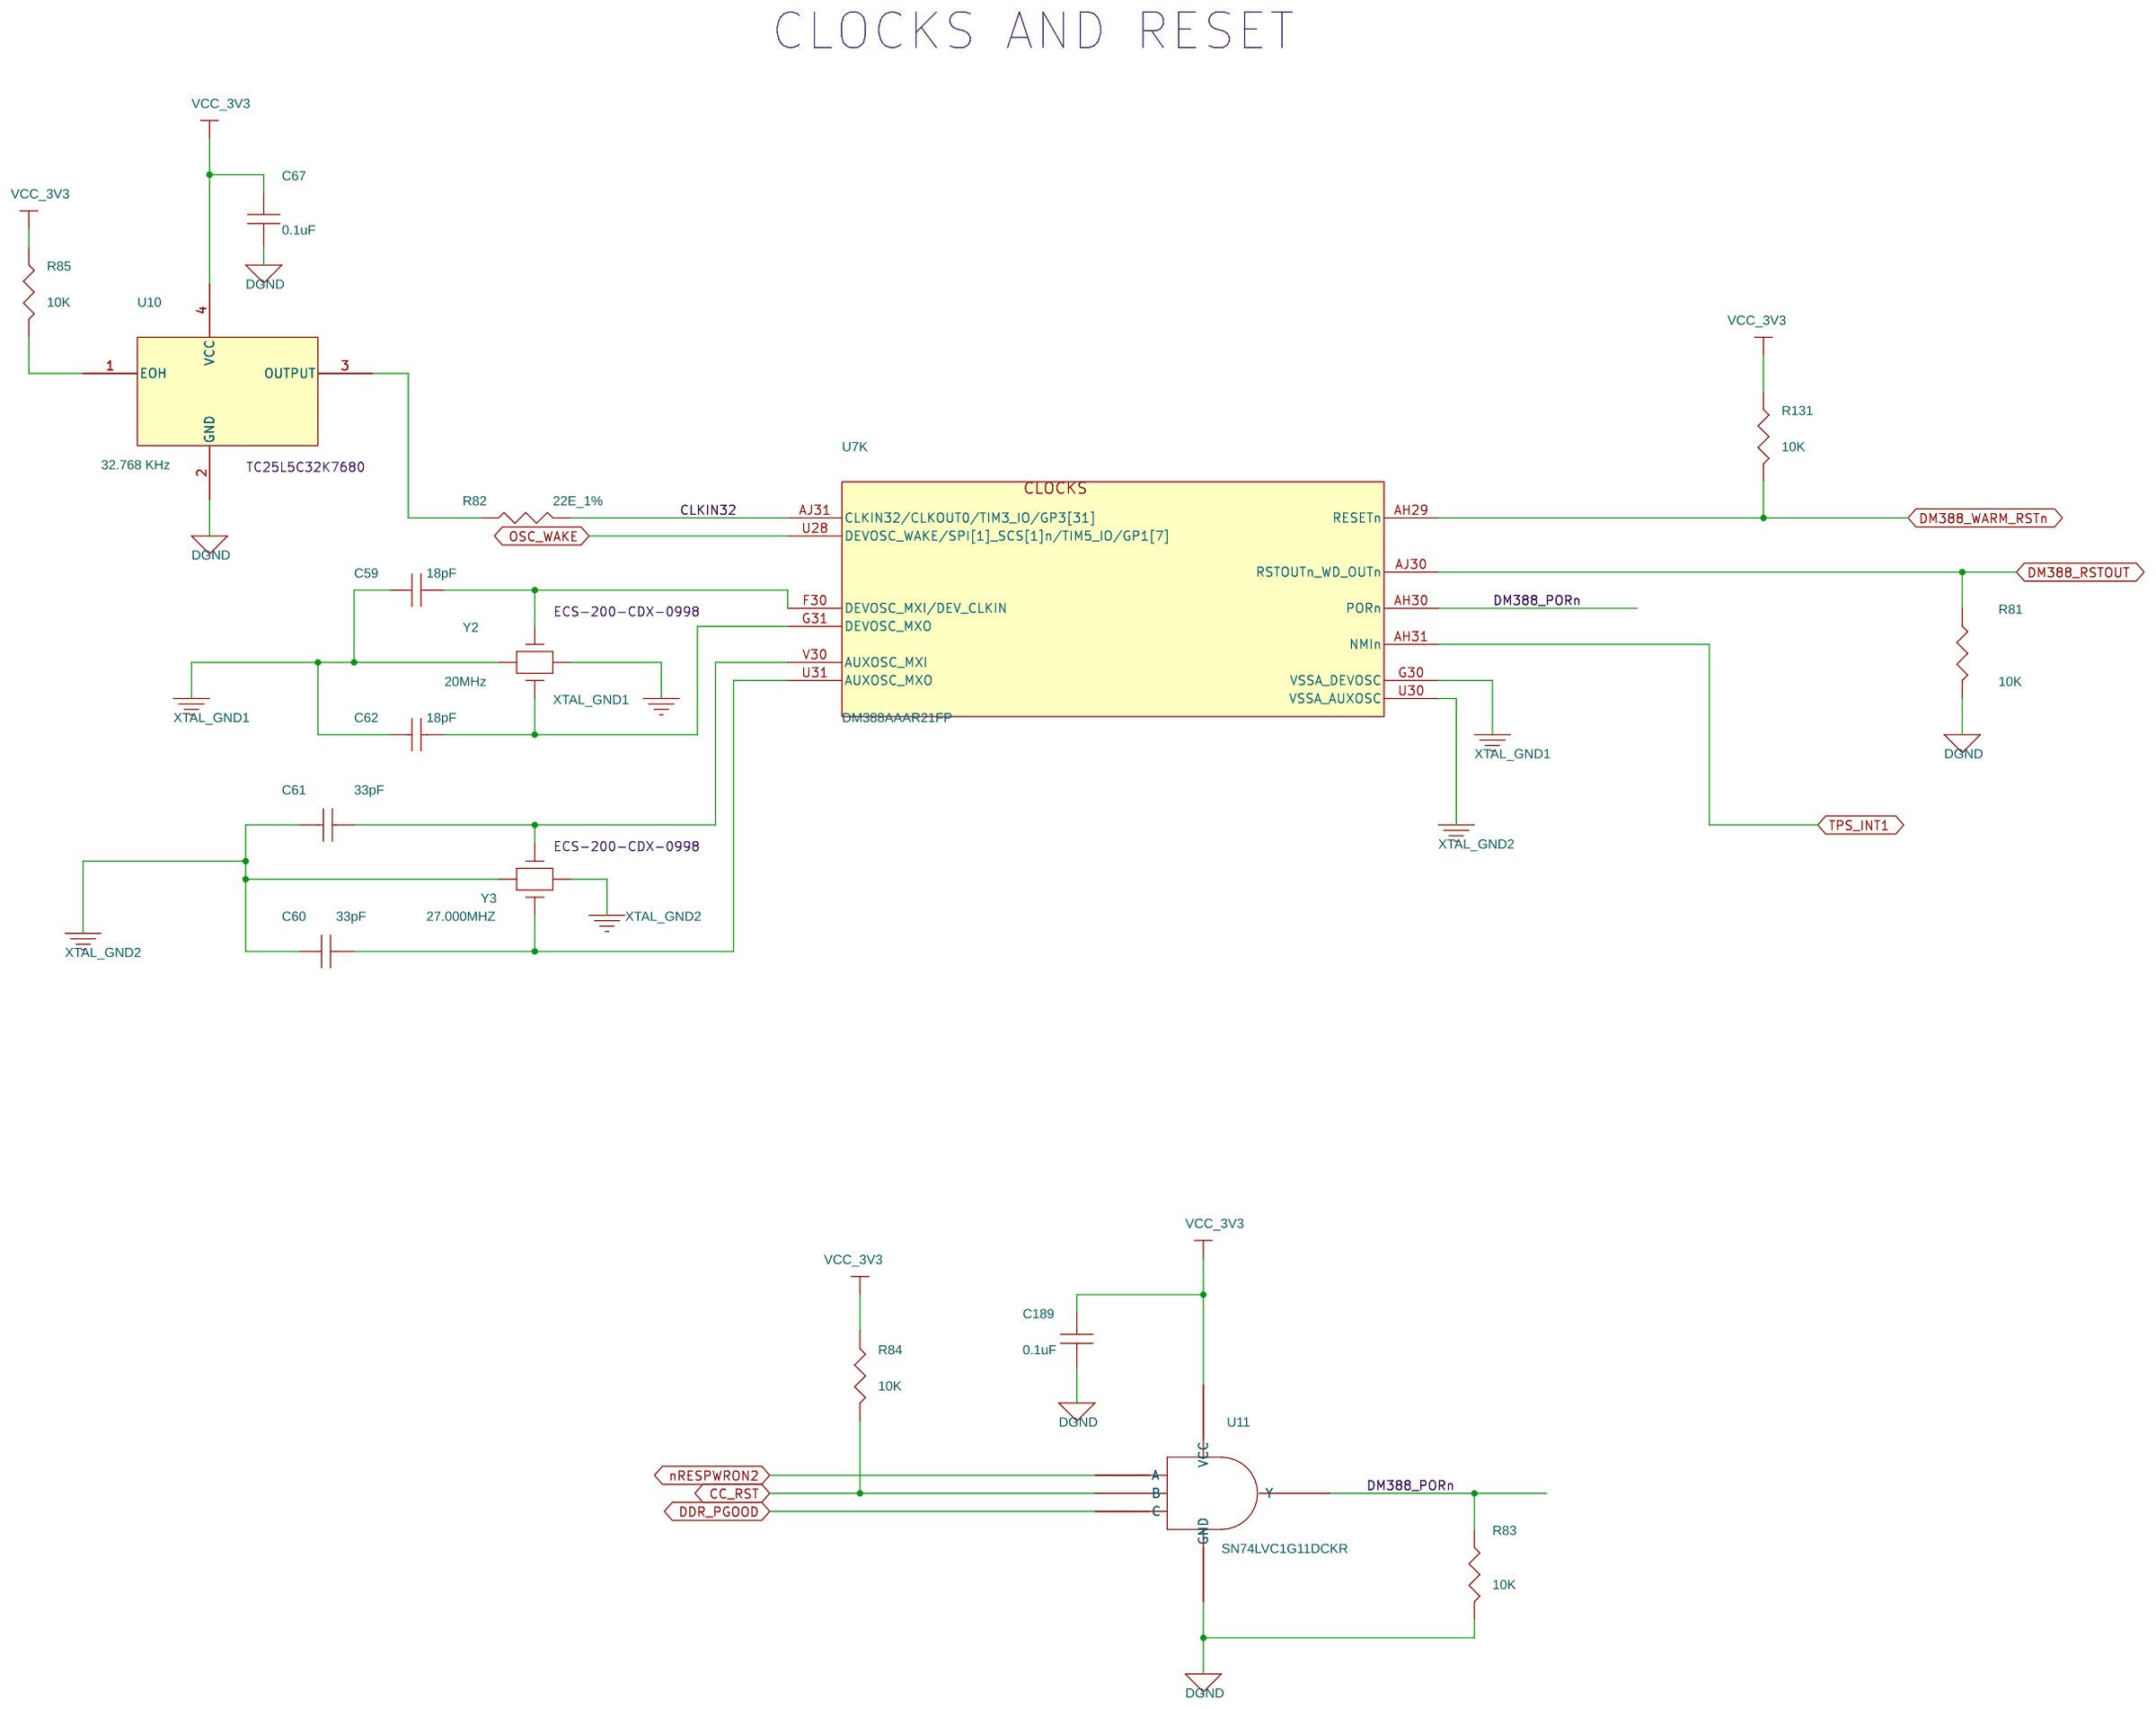
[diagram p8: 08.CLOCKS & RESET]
10 09.NAND FLASH,BOOTMODE & GPIOs: size C; title: NAND FLASH,BOOTMODE & GPIOs
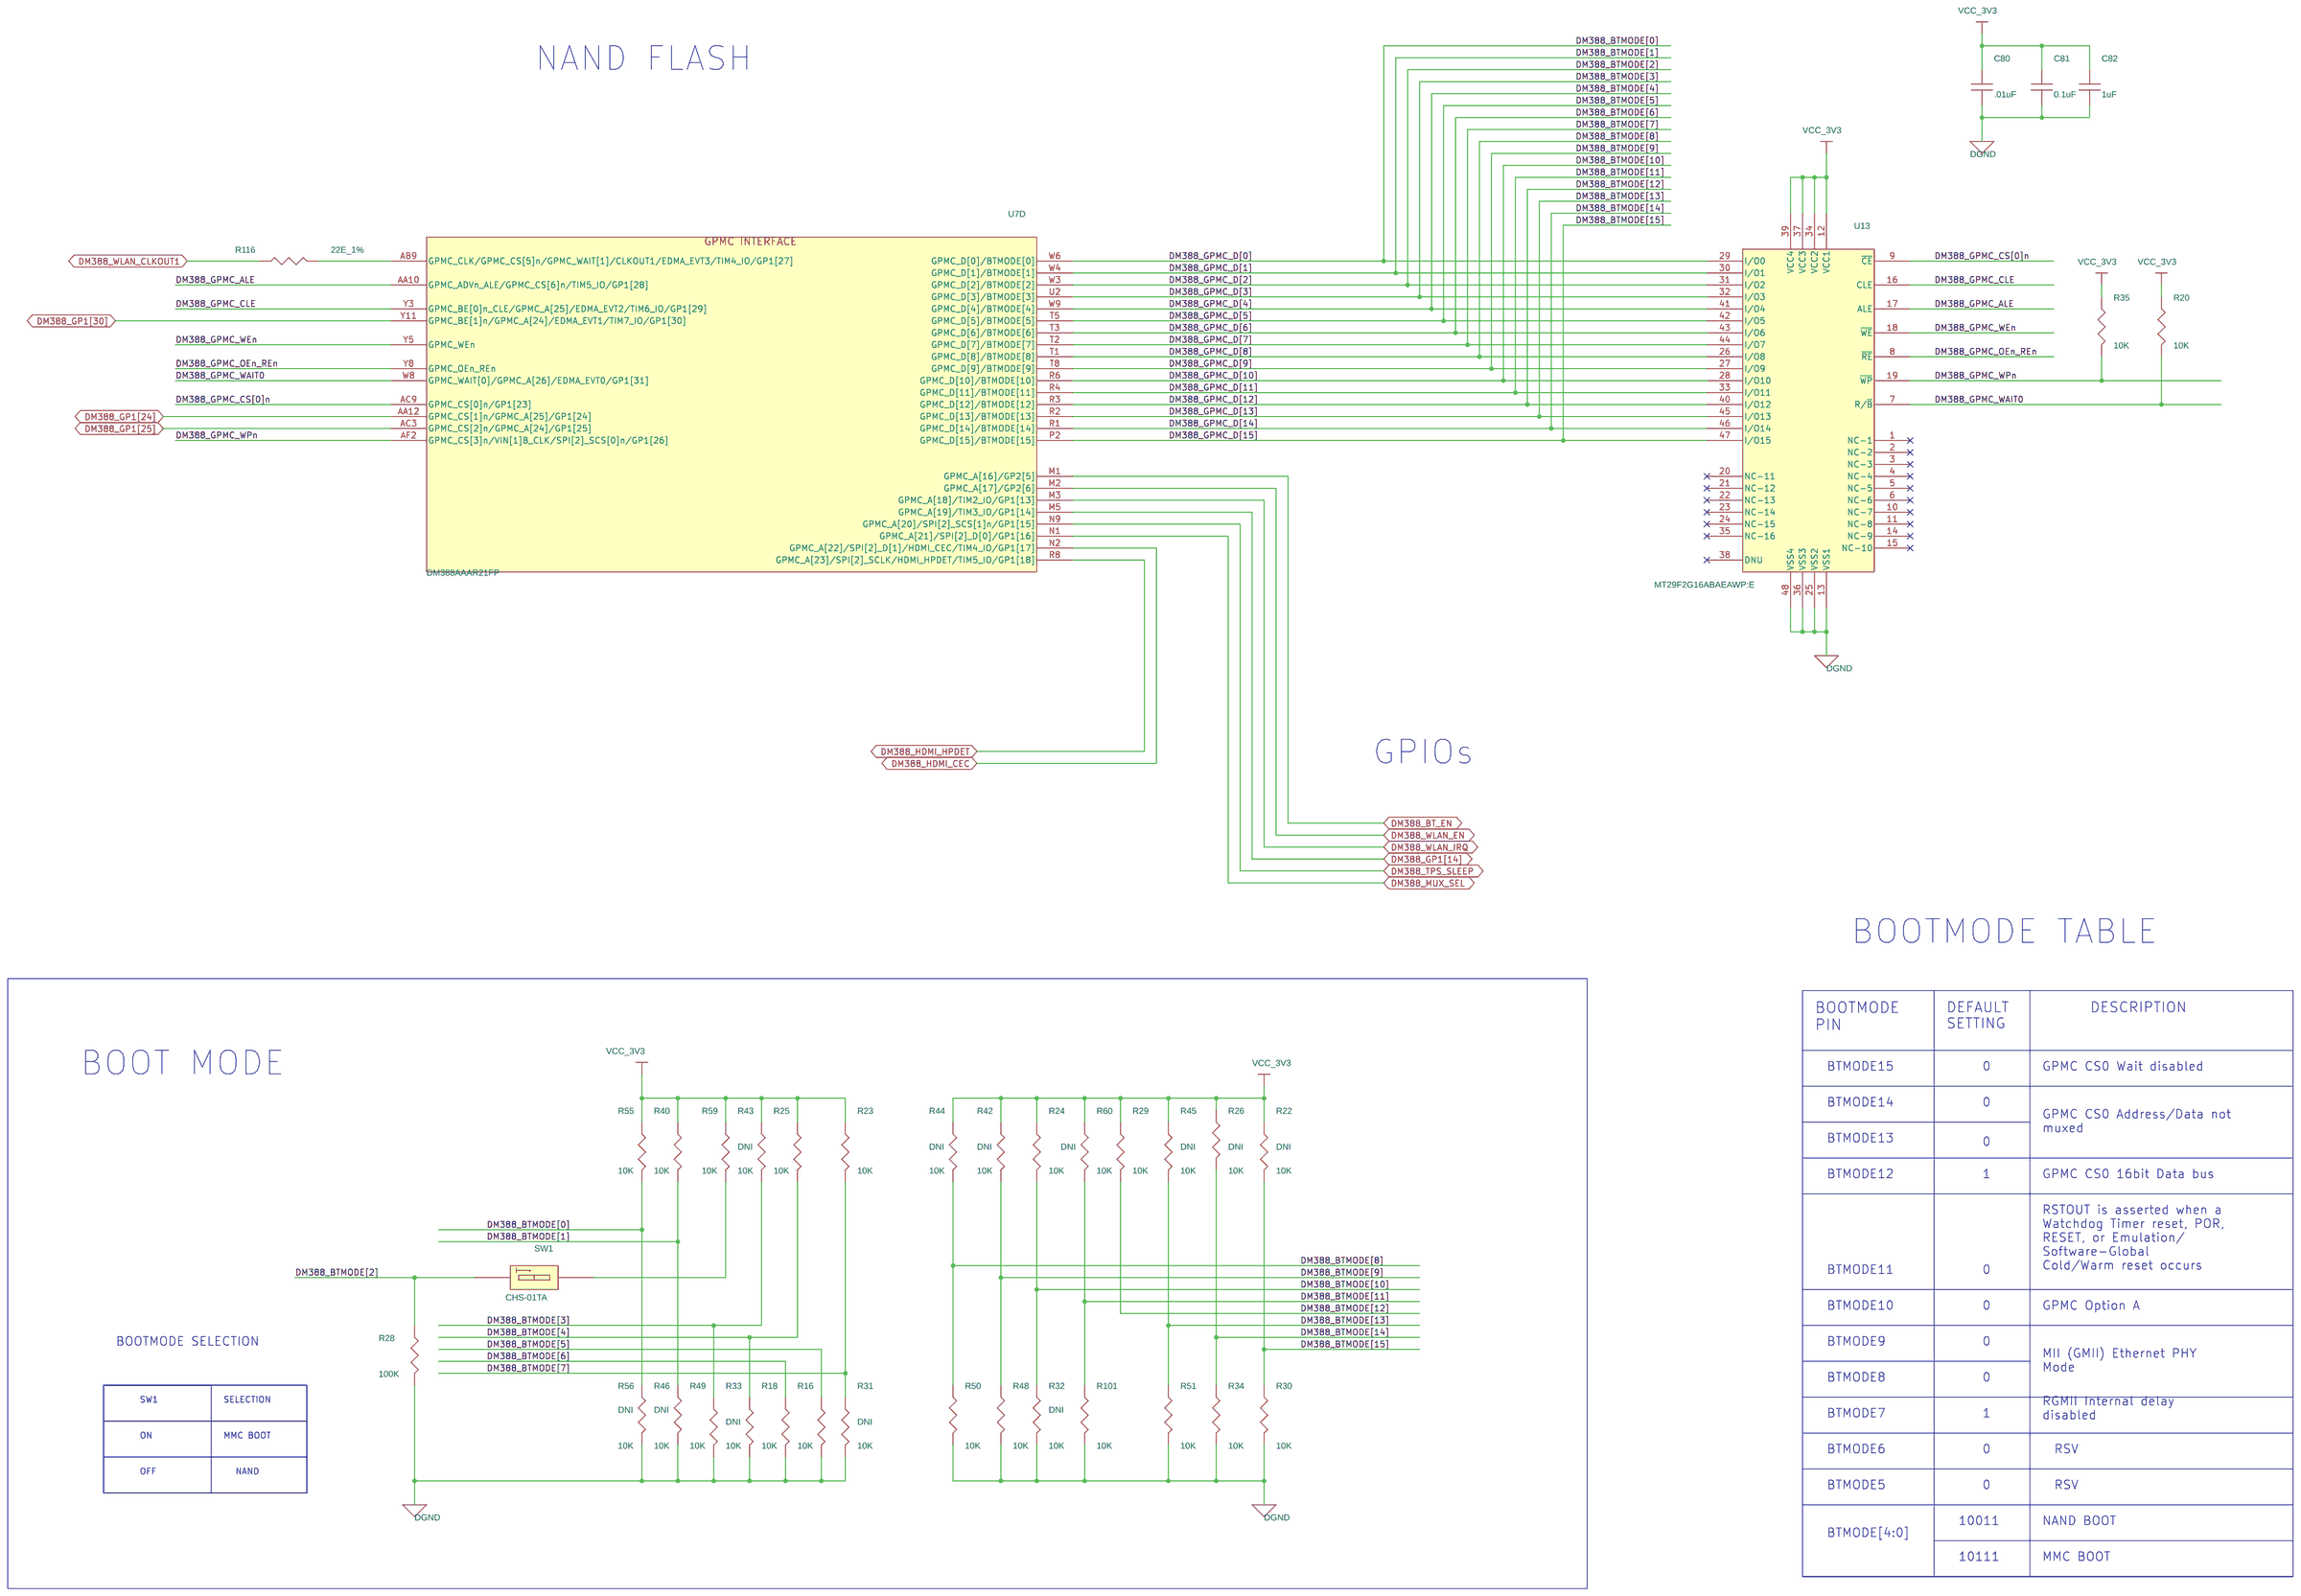
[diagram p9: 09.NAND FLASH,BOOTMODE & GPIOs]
11 10.DDR3 INTERFACE: size C; title: DDR3 INTERFACE
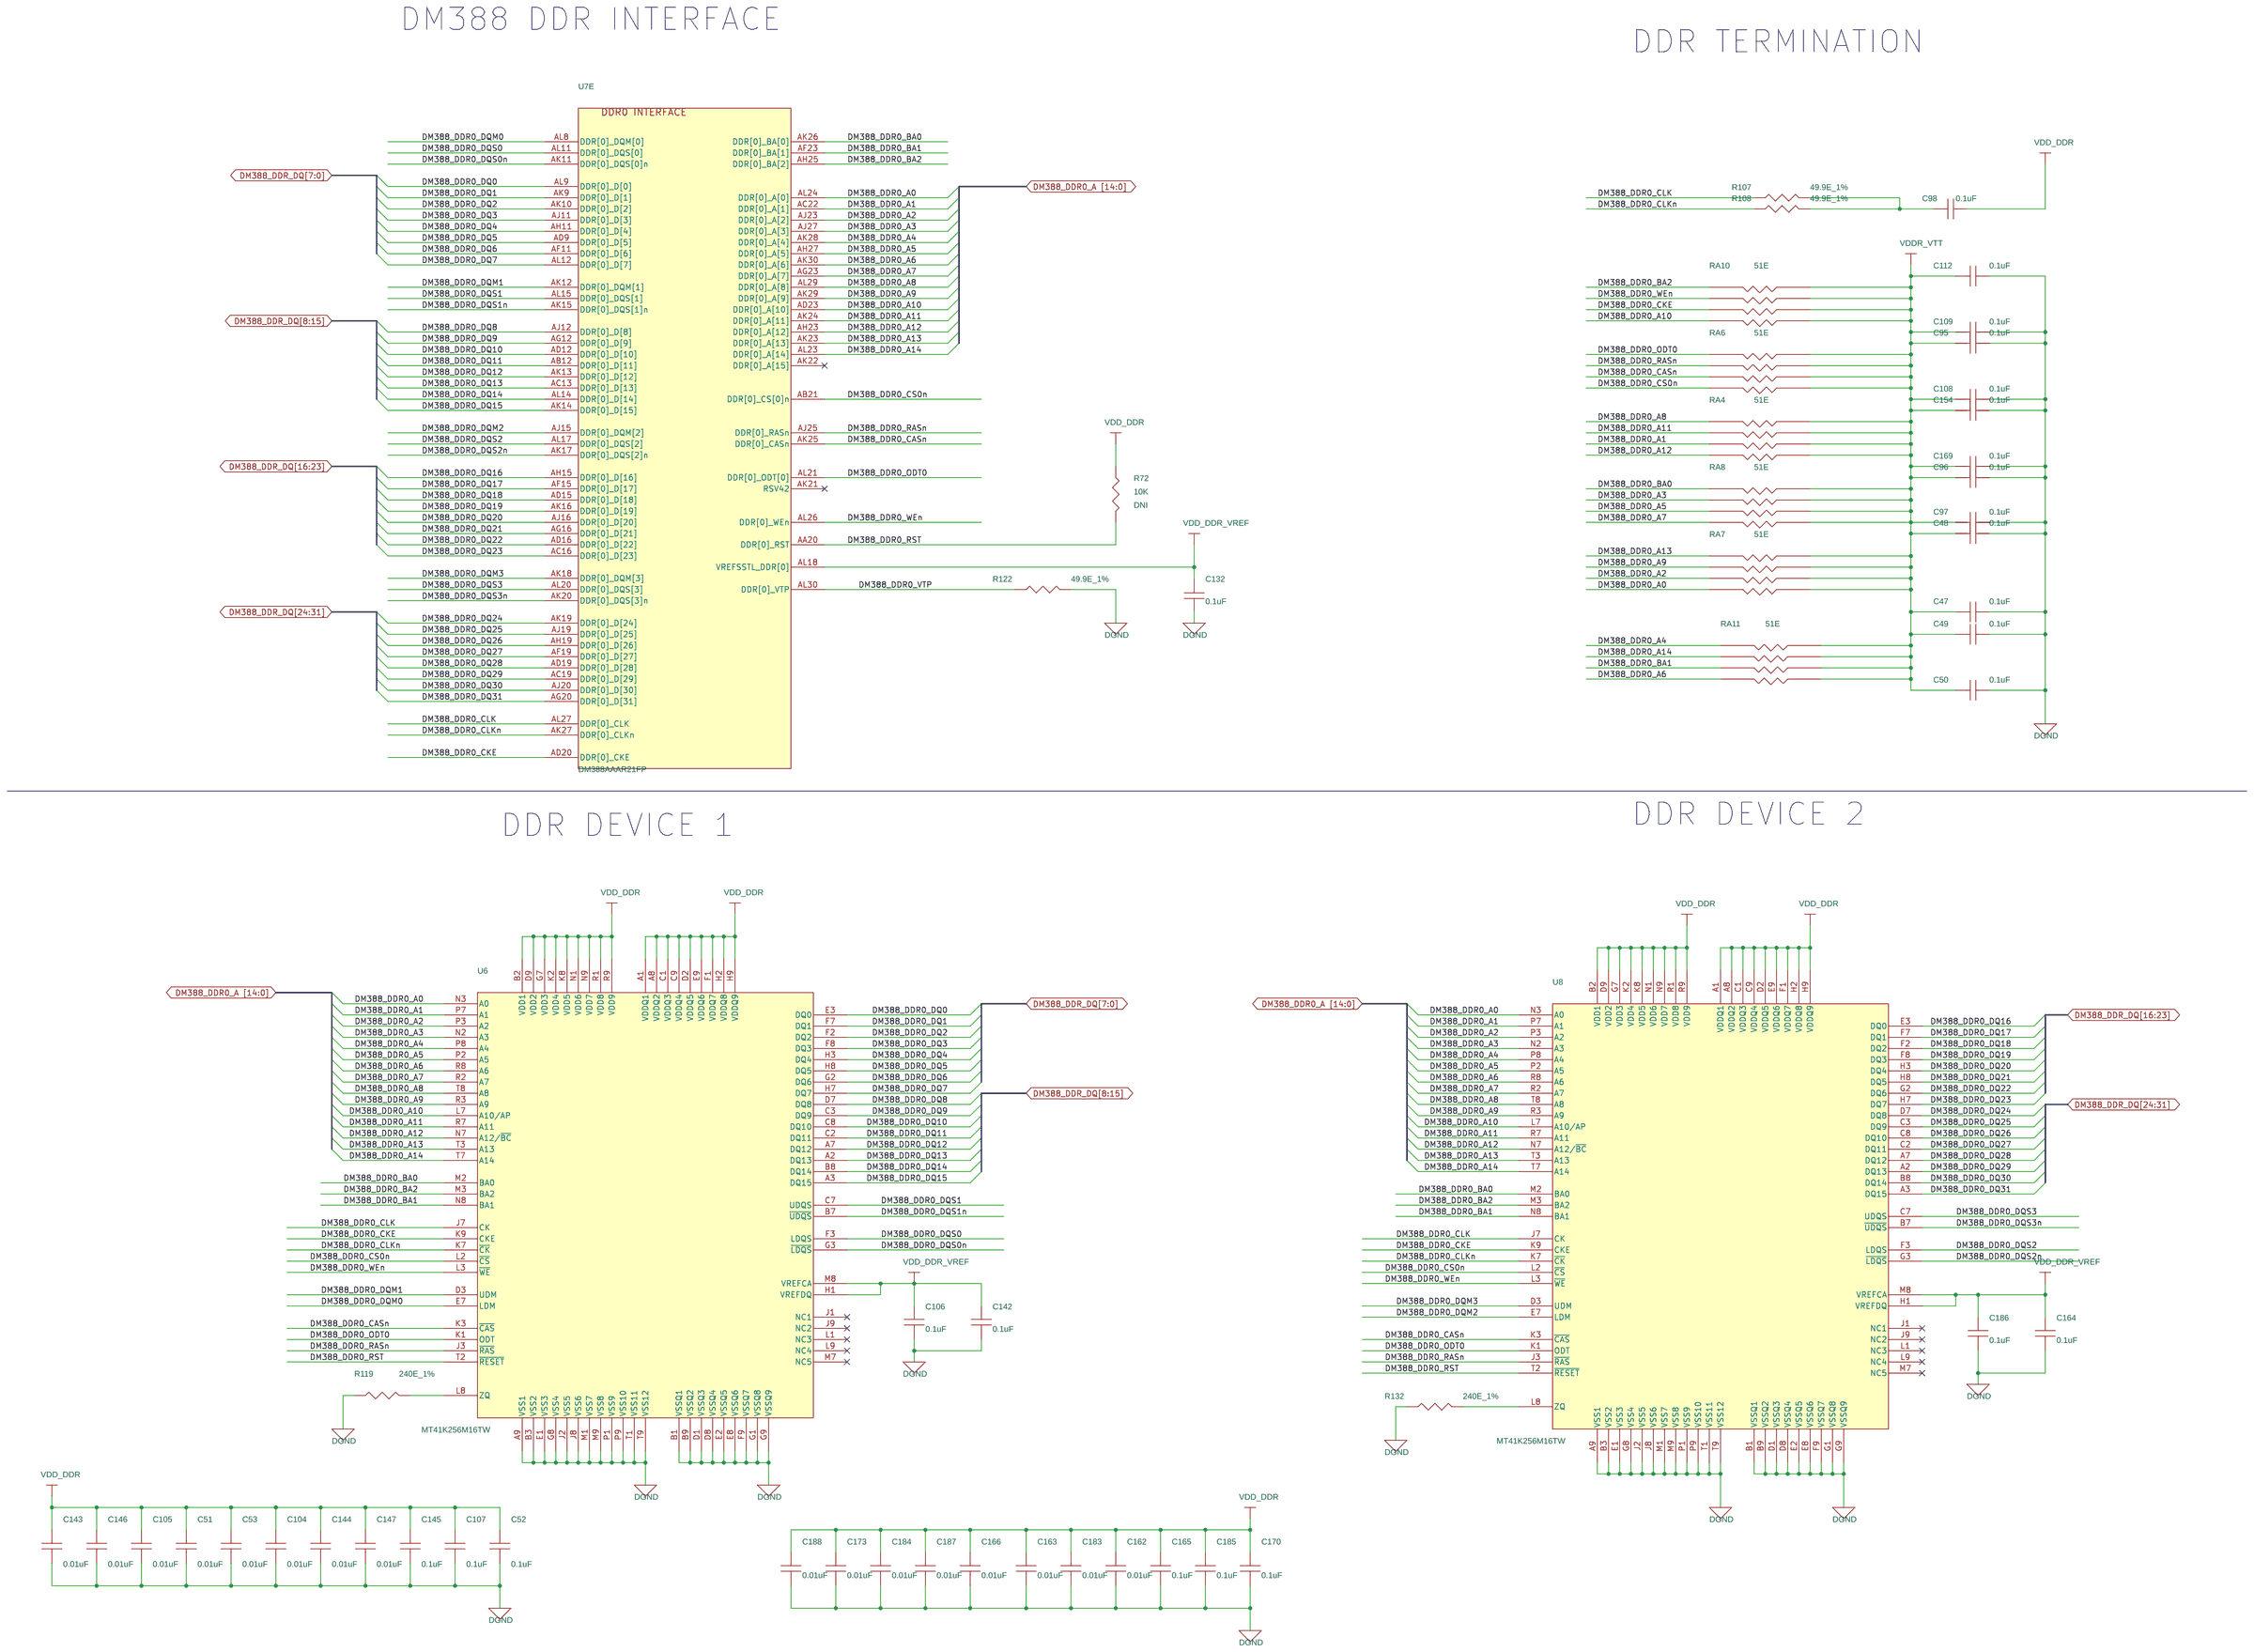
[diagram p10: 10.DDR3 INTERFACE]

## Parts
sheet 08.CLOCKS & RESET
C59  18pF  [CAP0402]
C60  33pF  [CAP0402]
C61  33pF  [CAP0402]
C62  18pF  [CAP0402]
C67  0.1uF  [CAP0402]
C189  0.1uF  [CAP0402]
R81  10K  [RES0402]
R82  22E_1%  [RES0402]
R83  10K  [RES0402]
R84  10K  [RES0402]
R85  10K  [RES0402]
R131  10K  [RES0402]
U10  32.768 KHz  [OSC4_TC25M5I32_110X90_SMD]
U11  SN74LVC1G11DCKR  [SC70-6]
Y2  20MHz  [XTAL4_ECS_130X100_SMD]
Y3  27.000MHZ  [XTAL4_FA-238V_130X105_SMD]
sheet 09.NAND FLASH,BOOTMODE & GPIOs
C80  .01uF  [CAP0402]
C81  0.1uF  [CAP0402]
C82  1uF  [CAP0402]
R16  10K  [RES0402]
R18  10K  [RES0402]
R20  10K  [RES0402]
R22  10K  [RES0402]
R23  10K  [RES0402]
R24  10K  [RES0402]
R25  10K  [RES0402]
R26  10K  [RES0402]
R28  100K  [RES0402]
R29  10K  [RES0402]
R30  10K  [RES0402]
R31  10K  [RES0402]
R32  10K  [RES0402]
R33  10K  [RES0402]
R34  10K  [RES0402]
R35  10K  [RES0402]
R40  10K  [RES0402]
R42  10K  [RES0402]
R43  10K  [RES0402]
R44  10K  [RES0402]
R45  10K  [RES0402]
R46  10K  [RES0402]
R48  10K  [RES0402]
R49  10K  [RES0402]
R50  10K  [RES0402]
R51  10K  [RES0402]
R55  10K  [RES0402]
R56  10K  [RES0402]
R59  10K  [RES0402]
R60  10K  [RES0402]
R101  10K  [RES0402]
R116  22E_1%  [RES0402]
SW1  CHS-01TA  [SW2_CHS-01TA_SMD]
U13  MT29F2G16ABAEAWP:E  [TSOP48_19-68_730X480]
sheet 10.DDR3 INTERFACE
C47  0.1uF  [CAP0402]
C48  0.1uF  [CAP0402]
C49  0.1uF  [CAP0402]
C50  0.1uF  [CAP0402]
C51  0.01uF  [CAP0402]
C52  0.1uF  [CAP0402]
C53  0.01uF  [CAP0402]
C95  0.1uF  [CAP0402]
C96  0.1uF  [CAP0402]
C97  0.1uF  [CAP0402]
C98  0.1uF  [CAP0402]
C104  0.01uF  [CAP0402]
C105  0.01uF  [CAP0402]
C106  0.1uF  [CAP0402]
C107  0.1uF  [CAP0402]
C108  0.1uF  [CAP0402]
C109  0.1uF  [CAP0402]
C112  0.1uF  [CAP0402]
C132  0.1uF  [CAP0402]
C142  0.1uF  [CAP0402]
C143  0.01uF  [CAP0402]
C144  0.01uF  [CAP0402]
C145  0.1uF  [CAP0402]
C146  0.01uF  [CAP0402]
C147  0.01uF  [CAP0402]
C154  0.1uF  [CAP0402]
C162  0.01uF  [CAP0402]
C163  0.01uF  [CAP0402]
C164  0.1uF  [CAP0402]
C165  0.1uF  [CAP0402]
C166  0.01uF  [CAP0402]
C169  0.1uF  [CAP0402]
C170  0.1uF  [CAP0402]
C173  0.01uF  [CAP0402]
C183  0.01uF  [CAP0402]
C184  0.01uF  [CAP0402]
C185  0.1uF  [CAP0402]
C186  0.1uF  [CAP0402]
C187  0.01uF  [CAP0402]
C188  0.01uF  [CAP0402]
R72  10K  [RES0402]
R107  49.9E_1%  [RES0402]
R108  49.9E_1%  [RES0402]
R119  240E_1%  [RES0402]
R122  49.9E_1%  [RES0402]
R132  240E_1%  [RES0402]
RA4  51E  [RESA_YC124_0402-4]
RA6  51E  [RESA_YC124_0402-4]
RA7  51E  [RESA_YC124_0402-4]
RA8  51E  [RESA_YC124_0402-4]
RA10  51E  [RESA_YC124_0402-4]
RA11  51E  [RESA_YC124_0402-4]
U6  MT41K256M16TW  [FBGA96_31-49_560X320]
U8  MT41K256M16TW  [FBGA96_31-49_560X320]
sheet 19.ETHERNET,HDMI & USB
U7  DM388AAAR21FP  [BGA609_19-68_635X635]  (sections A,B,C,D,E,F,G,H,I,J,K,L,M,N)
sheet 22.HARDWARE SCHEMATICS
FID1  FID_40X80  [Fiducial10-20]
FID2  FID_40X80  [Fiducial10-20]
FID3  FID_40X80  [Fiducial10-20]
FID4  FID_40X80  [Fiducial10-20]
FID5  FID_40X80  [Fiducial10-20]
FID6  FID_40X80  [Fiducial10-20]
H4  SDSDQM-008G-B35  [Keystone_1902C]
LBL1  Size: 0.9" x 0.12 "  [Label_650x200]
LBL2  Size: 0.55" x 0.12 "  [Label_650x200]
Logo1  Texas Intruments  [TI_Stacked_Overlay_Small]
Logo2  For Evaluation only; not FCC approved for resale  [FCC_disclaimer]
Logo3  Pb-Free  [Pb-Free_Overlay_Small]
PCB1  PCB
ZZ1  The boards and components must be baked before assembly  [AssemblyNoteLabel]
ZZ2  Provide serial numbers to the assembled boards for identification  [AssemblyNoteLabel]
ZZ3  Please carry out the cold points check verification and provide the report for each assembled board  [AssemblyNoteLabel]
ZZ4  The assembled board are wrapped in ESD Covers(individual) and packed securely before shipment.  [AssemblyNoteLabel]
ZZ5  All MSL components should be baked as per JEDEC standard  [AssemblyNoteLabel]
ZZ6  PCB should be baked at 120 degree for 8 hours  [AssemblyNoteLabel]
ZZ7  These assemblies must comply with workmanship standards IPC-A-610 Class 2, unless otherwise specified.  [AssemblyNoteLabel]
ZZ8  These assemblies are ESD sensitive, ESD precautions shall be observed.  [AssemblyNoteLabel]
ZZ9  These assemblies must be clean and free from flux and all contaminants. Use of no clean flux is not acceptable.  [AssemblyNoteLabel]

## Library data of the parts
C59 C62 = CAP: CAP CERAMIC 18pF 50V 5% COG 0402; Chkd/date: VASANTHA/150514; Crtd /date: BALACHANDAR/150514; Custom_Duty: 15%; Customs_HS_Code: 85322990; Distributor_name: DIGIKEY; Distributor_part_number: 490-5858-1-ND; Height: 0.55MM; Mfr_name: MURATA; Mfr_part_number: GRM1555C1H180JA01D; Mistral Part No: 120014050002-R; Package: 0402; Part_type: CAPACITORS\CERAMIC; Project: HUMANWARE_PHOENIX; RoHS: RoHS; Temperature: -55°C+125°C; Tolerance: 5%; Voltage: 50V; Wattage: NA; Weight: NA; Datasheet: Y:\MIS_DATABASE\DATASHEETS\CAPACITORS\GRM188SERIES.PDF
C60 C61 = CAP: CAP CERAMIC 33pF 50V 5% NP0 0402; Chkd/date: NAVEED/241114; Crtd /date: VASANTHA/101114; Cust_part_number: 1500-80019E; Custom_Duty: 15%; Customs_HS_Code: 85322990; Distributor_name: DIGIKEY; Distributor_part_number: 311-1020-1-ND; Height: 0.55MM; Mfr_name: YAGEO AMERICA; Mfr_part_number: CC0402JRNPO9BN330; Mistral Part No: 120014110006-R; Package: 0402; Part_type: CAPACITORS\CERAMIC; Project: GALILEO_EVM; RoHS: RoHS; Temperature: -55°C+125°C; Tolerance: 5%; Voltage: 50V; Wattage: NA; Weight: NA; Datasheet: Y:\MIS_DATABASE\DATASHEETS\CAPACITORS\YACC0603.PDF
C47-C50 C52 C67 C81 C95-C98 C106-C109 C112 C132 C142 C145 C154 C164 C165 C169 C170 C185 C186 C189 = CAP: CAP CERAMIC 0.1uF 16V 10% X7R 0402; Alternate_mfr_name_A: KEMET; Alternate_mfr_part_number_A: C0402C104K4RACT; Chkd/date: MAZHAR/281108; Crtd /date: MAZHAR/030907; Cust_part_number: 1500-80042E; Custom_Duty: 15%; Customs_HS_Code: 85322990; Distributor_name: DIGIKEY; Distributor_name_A: DIGIKEY; Distributor_part_number: 490-3261-1-ND; Distributor_part_number_A: 399-3521-1-ND; Height: 0.55MM; Mfr_name: MURATA; Mfr_part_number: GRM155R71C104KA88D; Mistral Part No: 120009030060-R; Package: 0402; Part_type: CAPACITORS\CERAMIC; Project: SMART VIEW_IP CAMERA; Tolerance: 10%; Voltage: 16V; Wattage: NA; Weight: NA; Datasheet: Y:\MIS_DATABASE\DATASHEETS\CAPACITORS\GRM188SERIES.PDF
R16 R18 R20 R23-R25 R29 R30 R34 R35 R40 R48-R51 R55 R59 R81 R83-R85 R101 R131 = RESISTOR: RES 10K 1/16W 5% 0402; Alternate_mfr_name_A: AVX CORPORATION; Alternate_mfr_name_B: PANASONIC-ECG-ECG; Alternate_mfr_name_C: YAGEO AMERICA; Alternate_mfr_name_D: WALSIN; Alternate_mfr_part_number_A: CR05-103J-H; Alternate_mfr_part_number_B: ERJ-2GEJ103X; Alternate_mfr_part_number_C: 9C04021A1002JLHF3; Alternate_mfr_part_number_D: WR04X103_JT; Chkd/date: SHREESHAIL/061205; Crtd /date: MAZHAR/230805; Custom_Duty: 15%; Customs_HS_Code: 85332119; Distributor_name: DIGIKEY; Distributor_name_A: MOUSER; Distributor_name_B: DIGIKEY; Distributor_name_C: DIGIKEY; Distributor_name_D: NA; Distributor_part_number: 311-10KJRCT-ND; Distributor_part_number_A: 581-CR051002JT; Distributor_part_number_B: P10KJCT-ND; Distributor_part_number_C: 311-10KJCT-ND; Distributor_part_number_D: NA; Height: 0.40MM; Mfr_name: YAGEO AMERICA; Mfr_part_number: RC0402JR-0710KL; Mistral Part No: 110009030208-P; Package: 0402; Part_type: RESISTORS\FIXED; Project: HSE; RoHS: Pb-Free; Tolerance: 5%; Wattage: 1/16W; Datasheet: Y:\MIS_DATABASE\DATASHEETS\RESISTORS\YAGEO-RC0402.PDF
R82 R116 = RESISTOR: RES 22E 1/16W 1% 0402; Alternate_mfr_name_A: VISHAY; Alternate_mfr_part_number_A: CRCW040222R0FKED; Chkd/date: SUHAS/290910; Crtd /date: MAZHAR/090909; Cust_part_number: 4700-80047E; Custom_Duty: 15%; Customs_HS_Code: 85332119; Distributor_name: DIGIKEY; Distributor_name_A: DIGIKEY; Distributor_part_number: 311-22.0LRCT-ND; Distributor_part_number_A: 541-22.0LCT-ND; Height: 0.40MM; Mfr_name: YAGEO AMERICA; Mfr_part_number: RC0402FR-0722RL; Mistral Part No: 110009090004-P; Package: 0402; Part_type: RESISTORS\FIXED; Project: VMEFMCD; Remarks: In alternate datasheet it is RoHS COMPLIANT. Y:\MIS_DATABASE\DATASHEETS\RESISTORS\CRCW0402.PDF; RoHS: Pb-Free; Temperature: -55°C+155°C; Tolerance: 1%; Voltage: 50V; Wattage: 1/16W; Weight: 0.8g/1000pcs; Datasheet: Y:\MIS_DATABASE\DATASHEETS\RESISTORS\YAGEO-RC0402.PDF
U10 = OSC_TC25M5I32K7680: OSC 32.768KHz 3.3V SMD; Chkd/date: VASANTHA/230516; Crtd /date: VASANTHA/230516; Custom_Duty: 24%; Customs_HS_Code: 85437099; Distributor_name: DIGIKEY; Distributor_part_number: TC25L5C32K7680-ND; Height: 1.00MM; Mfr_name: CTS FREQUENCY CONTROL; Mfr_part_number: TC25L5C32K7680; Mistral Part No: 130016050034-R; Package: SMD; Part_type: OSCILLATORS; Project: TMDXCSK388; RoHS: RoHS; Temperature: -20°C+70°C; Tolerance: NA; Voltage: 3.3V; Wattage: NA; Weight: NA; Datasheet: Y:\MIS_DATABASE\DATASHEETS\MISC\CRY_OSC\TC25M5I32K7680.PDF
U11 = SN74LVC1G11DCKR_SC70-6: IC SINGLE 3-INPUT POSITIVE-AND GATE SC70-6; Chkd/date: SHREESHAIL/220506; Crtd /date: MAZHAR/150506; Custom_Duty: 15%; Customs_HS_Code: 85423100; Distributor_name: DIGIKEY; Distributor_part_number: 296-18066-1-ND; Height: 1.10MM; Mfr_name: TEXAS INSTRUMENTS; Mistral Part No: 141009030230-R; Part_type: ICS\DIGITAL\GATES; Project: VOCERA; RoHS: Sb/ Br FREE; Datasheet: Y:\MIS_DATABASE\DATASHEETS\ICS\DIGITAL\GATES\SN74LVC1G.PDF
Y2 = CRY4_13: CRY 20MHz SMD; Chkd/date: VASANTHA/300516; Crtd /date: VASANTHA/300516; Custom_Duty: 24%; Customs_HS_Code: 85439000; Distributor_name: DIGIKEY; Distributor_part_number: XC2074CT-ND; Height: 0.80MM; Mfr_name: ECS INC; Mfr_part_number: ECS-200-CDX-0998; Mistral Part No: 130016050043-R; Package: SMD; Part_type: CRYSTAL; Project: TMDXCSK388; RoHS: RoHS; Temperature: -60°C+105°C; Tolerance: NA; Voltage: NA; Wattage: NA; Weight: NA; Datasheet: Y:\MIS_DATABASE\DATASHEETS\MISC\CRY_OSC\ECS-200-CDX.PDF
Y3 = CRY4_13: CRY 27.000MHz SMD; Chkd/date: VASANTHA/130516; Crtd /date: VASANTHA/130516; Custom_Duty: 24%; Customs_HS_Code: 85439000; Distributor_name: DIGIKEY; Distributor_part_number: SER3693CT-ND; Height: 0.70MM; Mfr_name: EPSON; Mfr_part_number: FA-23827.0000MB-C3; Mistral Part No: 130016050025-R; Package: SMD; Part_type: CRYSTAL; Project: TMDXCSK368; RoHS: RoHS; Temperature: -40°C+85°C; Tolerance: NA; Voltage: NA; Wattage: NA; Weight: NA; Datasheet: Y:\MIS_DATABASEY:\MIS_DATABASE\DATASHEETS\MISC\CRY_OSC\FA238V-238-tax3225.PDF\DATASHEETS\MISC\CRY_OSC\FA238V-238-tax3225.PDF
C51 C53 C80 C104 C105 C143 C144 C146 C147 C162 C163 C166 C173 C183 C184 C187 C188 = CAP: CAP CERAMIC 10000pF 10V 10% X7R 0402; Chkd/date: VASANTHA/120516; Crtd /date: VASANTHA/120516; Custom_Duty: 15%; Customs_HS_Code: 85322990; Distributor_name: DIGIKEY; Distributor_part_number: 1276-1502-1-ND; Height: 0.55MM; Mfr_name: SAMSUNG ELECTRO MECHANIC; Mfr_part_number: CL05B103KP5NNNC; Mistral Part No: 120016050007-R; Package: 0402; Part_type: CAPACITORS\CERAMIC; Project: TMDXCSK368; RoHS: RoHS; Temperature: -55°C+125°C; Tolerance: 10%; Voltage: 10V; Wattage: NA; Weight: NA; Datasheet: Y:\MIS_DATABASE\DATASHEETS\CAPACITORS\CL_SERIES.PDF
C82 = CAP: CAP CERAMIC 1uF 10V 10% X5R 0402; Chkd/date: SHREESHAIL/290507; Crtd /date: MAZHAR/290806; Custom_Duty: 15%; Customs_HS_Code: 85322990; Distributor_name: DIGIKEY; Distributor_part_number: 490-3890-1-ND; Height: 0.55MM; Mfr_name: MURATA; Mfr_part_number: GRM155R61A105KE15D; Mistral Part No: 120009030264; Package: 0402; Part_type: CAPACITORS\CERAMIC; Project: SVDO_RMB_MMA; Tolerance: 10%; Voltage: 10V; Datasheet: Y:\MIS_DATABASE\DATASHEETS\CAPACITORS\GRM188SERIES.PDF
R22 R26 R31-R33 R42-R46 R56 R60 R72 = RESISTOR: RES 10K 1/16W 5% 0402; Alternate_mfr_name_A: AVX CORPORATION; Alternate_mfr_name_B: PANASONIC-ECG-ECG; Alternate_mfr_name_C: YAGEO AMERICA; Alternate_mfr_name_D: WALSIN; Alternate_mfr_part_number_A: CR05-103J-H; Alternate_mfr_part_number_B: ERJ-2GEJ103X; Alternate_mfr_part_number_C: 9C04021A1002JLHF3; Alternate_mfr_part_number_D: WR04X103_JT; Chkd/date: SHREESHAIL/061205; Crtd /date: MAZHAR/230805; Custom_Duty: 15%; Customs_HS_Code: 85332119; Distributor_name: DIGIKEY; Distributor_name_A: MOUSER; Distributor_name_B: DIGIKEY; Distributor_name_C: DIGIKEY; Distributor_name_D: NA; Distributor_part_number: 311-10KJRCT-ND; Distributor_part_number_A: 581-CR051002JT; Distributor_part_number_B: P10KJCT-ND; Distributor_part_number_C: 311-10KJCT-ND; Distributor_part_number_D: NA; Height: 0.40MM; Loading: DNI; Mfr_name: YAGEO AMERICA; Mfr_part_number: RC0402JR-0710KL; Mistral Part No: 110009030208-P; Package: 0402; Part_type: RESISTORS\FIXED; Project: HSE; RoHS: Pb-Free; Tolerance: 5%; Wattage: 1/16W; Datasheet: Y:\MIS_DATABASE\DATASHEETS\RESISTORS\YAGEO-RC0402.PDF
R28 = RESISTOR: RES 100K 1/16W 5% 0402; Chkd/date: VASANTHA/130516; Crtd /date: VASANTHA/130516; Custom_Duty: 15%; Customs_HS_Code: 85332119; Distributor_name: DIGIKEY; Distributor_part_number: A121521CT-ND; Height: 0.40MM; Mfr_name: TE CONNECTIVITY; Mfr_part_number: CRG0402J100K/10; Mistral Part No: 110011060002-R; Package: 0402; Part_type: RESISTORS\FIXED; Project: TMDXCSK368; RoHS: RoHS; Temperature: -55°C+125°C; Tolerance: 5%; Voltage: NA; Wattage: 1/16W; Weight: NA; Datasheet: Y:\MIS_DATABASE\DATASHEETS\RESISTORS\CRG-SERIES.PDF
SW1 = SW2_CHS-01TA: SWITCH SLIDE SPST SMD; Chkd/date: VASANTHA/100516; Crtd /date: VASANTHA/100516; Custom_Duty: 24%; Customs_HS_Code: 85369090; Distributor_name: DIGIKEY; Distributor_part_number: 563-1003-1-ND; Height: 2.50MM; Mfr_name: COPAL ELECTRONICS; Mistral Part No: 130016050015-R; Package: SMD; Part_type: ELECTRO-MECHANICAL\SWITCH; Project: AMBISCOPE; RoHS: RoHS; Temperature: -40°C+85°C; Tolerance: NA; Voltage: NA; Wattage: NA; Weight: NA; Datasheet: Y:\MIS_DATABASE\DATASHEETS\MISC\SWITCHES\CHSSER.PDF
U13 = MT29F2G16ABAEAWP_TSOP48: IC FLASH MEMORY 2-GBIT 16BIT 3.3V TSOP48; Chkd/date: NAVEED/130715; Crtd /date: BAVISH/150611; Custom_Duty: 15%; Customs_HS_Code: 85423100; Distributor_name: NA; Distributor_part_number: NA; Height: 1.20MM; Mfr_name: MICRON; Mistral Part No: 141111060004-R; Package: TSOP48; Part_type: ICS\DIGITAL\MEMORY; Project: DIGITAL_SIGNAGE; RoHS: RoHS; Temperature: 0°C+70°C; Tolerance: NA; Voltage: 3.3V; Wattage: NA; Weight: NA; Datasheet: Y:\MIS_DATABASE\DATASHEETS\ICS\MEMORY\MT29F2G16ABAEAWP.PDF
R107 R108 R122 = RESISTOR: RES 49.9E 1/16W 1% 0402; Chkd/date: JEBRAN/050815; Crtd /date: JEBRAN/050815; Custom_Duty: 15%; Customs_HS_Code: 85332119; Distributor_name: DIGIKEY; Distributor_part_number: 311-49.9LRCT-ND; Height: 0.40MM; Mfr_name: YAGEO AMERICA; Mfr_part_number: RC0402FR-0749R9L; Mistral Part No: 110015080002-R; Package: 0402; Part_type: RESISTORS\FIXED; Project: PDLU; RoHS: RoHS; Temperature: -55°C+155°C; Tolerance: 1%; Voltage: NA; Wattage: 1/16W; Weight: NA; Datasheet: Y:\MIS_DATABASE\DATASHEETS\CAPACITORS\YAGEO-SERIES.PDF
R119 R132 = RESISTOR: RES 240E 1/16W 1% 0402; Chkd/date: VASANTHA/140714; Crtd /date: NAVEED/200614; Custom_Duty: 15%; Customs_HS_Code: 85332119; Distributor_name: DIGIKEY; Distributor_part_number: RMCF0402FT240RCT-ND; Height: 0.40MM; Mfr_name: STACKPOLE ELECTRONICS; Mfr_part_number: RMCF0402FT240R; Mistral Part No: 110014060051-R; Package: 0402; Part_type: RESISTORS\FIXED; Project: AEGIS_POM; RoHS: RoHS; Temperature: -55°C+155°C; Tolerance: 1%; Voltage: NA; Wattage: 1/16W; Weight: NA; Datasheet: Y:\MIS_DATABASE\DATASHEETS\RESISTORS\RMCF-SERIES.PDF
RA4 RA6-RA8 RA10 RA11 = RESARR_ISO4: RES ARRAY 51E 62.5mW 5% SMD; Chkd/date: VASANTHA/250516; Crtd /date: VASANTHA/250516; Distributor_name: DIGIKEY; Distributor_part_number: YC124J-51CT-ND; Height: 0.55MM; Mfr_name: YAGEO AMERICA; Mfr_part_number: YC124-JR-0751RL; Mistral Part No: 110016050015-R; Package: SMD; Part_type: RESISTORS\ARRAY; Project: TMDXCSK8127; RoHS: RoHS; Temperature: -55°C+155°C; Tolerance: 5%; Voltage: NA; Wattage: 62.5mW; Weight: NA; Datasheet: Y:\MIS_DATABASE\DATASHEETS\RESISTORS\YC-SERIES.PDF
U6 U8 = MT41K256M16HA_FBGA96: IC 256Mb DDR SDRAM FBGA96; Chkd/date: VASANTHA/190216; Crtd /date: VASANTHA/190216; Custom_Duty: 15%; Customs_HS_Code: 85423100; Distributor_name: NA; Distributor_part_number: NA; Height: 1.20MM; Mfr_name: MICRON; Mfr_part_number: MT41K256M16TW-107; Mistral Part No: 141116020004-P; Package: FBGA96; Part_type: ICS\DIGITAL\MEMORY; Project: DM368_EVM; RoHS: Pb-Free; Temperature: -0°C+95°C; Tolerance: NA; Voltage: NA; Wattage: NA; Weight: NA; Datasheet: Y:\MIS_DATABASE\DATASHEETS\ICS\MEMORY\MT41K-TW.PDF
U7 = DM385AAAR21F_BGA609: IC PROCESSOR DIGITAL MEDIA FCBGA609; Chkd/date: VASANTHA/170516; Color: Default; Crtd /date: VASANTHA/170516; Custom_Duty: 15%; Customs_HS_Code: 85423100; Distributor_name: NA; Distributor_part_number: NA; Height: 1.32MM; Location X-Coordinate: 0; Location Y-Coordinate: 0; Mfr_name: TEXAS INSTRUMENTS; Mistral Part No: 141216050002-R; Package: FCBGA609; Part_type: ICS\DIGITAL\MICROPROCESSOR; Power Pins Visible: False; Primitive: DEFAULT; Project: TMDXCSK388; RoHS: RoHS; Temperature: 0°C+95°C; Tolerance: NA; Voltage: NA; Wattage: NA; Weight: NA; Datasheet: Y:\MIS_DATABASE\DATASHEETS\ICS\DIGITAL\MICROCONTROLLER\DM385-88.PDF
FID1-FID6 = Fiducial
H4 = uSD_card: Sandisk 00090955 8Gb Class 4 Microsdhc Memory Card; Mfr_name: SanDisk
LBL1 LBL2 = THT-14-423-10
Logo1 = TI_Logo
Logo2 = FCC_disclaimer
Logo3 = Pb-Free
PCB1 = PCB
ZZ1-ZZ9 = AssemblyNoteLabel

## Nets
DGND: C47.1 C48.1 C49.1 C50.1 C51.2 C52.2 C53.2 C67.2 C80.2 C81.2 C82.2 C95.1 C96.1 C97.1 C104.2 C105.2 C106.2 C107.2 C108.1 C109.1 C112.1 C132.1 C142.2 C143.2 C144.2 C145.2 C146.2 C147.2 C154.1 C162.2 C163.2 C164.2 C165.2 C166.2 C169.1 C170.2 C173.2 C183.2 C184.2 C185.2 C186.2 C187.2 C188.2 C189.2 R16.2 R18.2 R28.2 R30.2 R31.2 R32.2 R33.2 R34.2 R46.2 R48.2 R49.2 R50.2 R51.2 R56.2 R81.2 R83.2 R101.2 R119.1 R122.2 R132.1 U6.A9(VSS1) U6.B1(VSSQ1) U6.B3(VSS2) U6.B9(VSSQ2) U6.D1(VSSQ3) U6.D8(VSSQ4) U6.E1(VSS3) U6.E2(VSSQ5) U6.E8(VSSQ6) U6.F9(VSSQ7) U6.G1(VSSQ8) U6.G8(VSS4) U6.G9(VSSQ9) U6.J2(VSS5) U6.J8(VSS6) U6.M1(VSS7) U6.M9(VSS8) U6.P1(VSS9) U6.P9(VSS10) U6.T1(VSS11) U6.T9(VSS12) U8.A9(VSS1) U8.B1(VSSQ1) U8.B3(VSS2) U8.B9(VSSQ2) U8.D1(VSSQ3) U8.D8(VSSQ4) U8.E1(VSS3) U8.E2(VSSQ5) U8.E8(VSSQ6) U8.F9(VSSQ7) U8.G1(VSSQ8) U8.G8(VSS4) U8.G9(VSSQ9) U8.J2(VSS5) U8.J8(VSS6) U8.M1(VSS7) U8.M9(VSS8) U8.P1(VSS9) U8.P9(VSS10) U8.T1(VSS11) U8.T9(VSS12) U10.2(GND) U11.2(GND) U13.13(VSS1) U13.25(VSS2) U13.36(VSS3) U13.48(VSS4) ; also on sheet 12 13 14 15 16 17 18 19 20 21
VCC_3V3: C67.1 C80.1 C81.1 C82.1 C189.1 R20.1 R22.1 R23.1 R24.1 R25.1 R26.1 R29.1 R35.1 R40.1 R42.1 R43.1 R44.1 R45.1 R55.1 R59.1 R60.1 R84.1 R85.1 R131.1 U10.4(VCC) U11.5(VCC) U13.12(VCC1) U13.34(VCC2) U13.37(VCC3) U13.39(VCC4) ; also on sheet 12 13 14 16 17 18 19 21 22
VDD_DDR: C51.1 C52.1 C53.1 C98.1 C104.1 C105.1 C107.1 C143.1 C144.1 C145.1 C146.1 C147.1 C162.1 C163.1 C165.1 C166.1 C170.1 C173.1 C183.1 C184.1 C185.1 C187.1 C188.1 R72.1 U6.A1(VDDQ1) U6.A8(VDDQ2) U6.B2(VDD1) U6.C1(VDDQ3) U6.C9(VDDQ4) U6.D2(VDDQ5) U6.D9(VDD2) U6.E9(VDDQ6) U6.F1(VDDQ7) U6.G7(VDD3) U6.H2(VDDQ8) U6.H9(VDDQ9) U6.K2(VDD4) U6.K8(VDD5) U6.N1(VDD6) U6.N9(VDD7) U6.R1(VDD8) U6.R9(VDD9) U8.A1(VDDQ1) U8.A8(VDDQ2) U8.B2(VDD1) U8.C1(VDDQ3) U8.C9(VDDQ4) U8.D2(VDDQ5) U8.D9(VDD2) U8.E9(VDDQ6) U8.F1(VDDQ7) U8.G7(VDD3) U8.H2(VDDQ8) U8.H9(VDDQ9) U8.K2(VDD4) U8.K8(VDD5) U8.N1(VDD6) U8.N9(VDD7) U8.R1(VDD8) U8.R9(VDD9) ; also on sheet 14 18
VDD_DDR_VREF: C106.1 C132.2 C142.1 C164.1 C186.1 U6.H1(VREFDQ) U6.M8(VREFCA) U7.AL18(VREFSSTL_DDR[0]) U8.H1(VREFDQ) U8.M8(VREFCA) ; also on sheet 18
VDDR_VTT: C47.2 C48.2 C49.2 C50.2 C95.2 C96.2 C97.2 C108.2 C109.2 C112.2 C154.2 C169.2 RA4.1 RA4.2 RA4.3 RA4.4 RA6.1 RA6.2 RA6.3 RA6.4 RA7.1 RA7.2 RA7.3 RA7.4 RA8.1 RA8.2 RA8.3 RA8.4 RA10.1 RA10.2 RA10.3 RA10.4 RA11.1 RA11.2 RA11.3 RA11.4 ; also on sheet 18
CC_RST: R84.2 U11.3(B) ; also on sheet 21
CLKIN32: R82.2 U7.AJ31(CLKIN32/CLKOUT0/TIM3_IO/GP3[31])
DDR_PGOOD: U11.6(C) ; also on sheet 18
DM388_BT_EN: U7.M1(GPMC_A[16]/GP2[5]) ; also on sheet 12
DM388_BTMODE[0]: R55.2 R56.1 U7.W6(GPMC_D[0]/BTMODE[0]) U13.29(I/O0)
DM388_BTMODE[1]: R40.2 R46.1 U7.W4(GPMC_D[1]/BTMODE[1]) U13.30(I/O1)
DM388_BTMODE[2]: R28.1 SW1.2 U7.W3(GPMC_D[2]/BTMODE[2]) U13.31(I/O2)
DM388_BTMODE[3]: R43.2 R49.1 U7.U2(GPMC_D[3]/BTMODE[3]) U13.32(I/O3)
DM388_BTMODE[4]: R25.2 R33.1 U7.W9(GPMC_D[4]/BTMODE[4]) U13.41(I/O4)
DM388_BTMODE[5]: R16.1 U7.T5(GPMC_D[5]/BTMODE[5]) U13.42(I/O5)
DM388_BTMODE[6]: R18.1 U7.T3(GPMC_D[6]/BTMODE[6]) U13.43(I/O6)
DM388_BTMODE[7]: R23.2 R31.1 U7.T2(GPMC_D[7]/BTMODE[7]) U13.44(I/O7)
DM388_BTMODE[8]: R44.2 R50.1 U7.T1(GPMC_D[8]/BTMODE[8]) U13.26(I/O8)
DM388_BTMODE[9]: R42.2 R48.1 U7.T8(GPMC_D[9]/BTMODE[9]) U13.27(I/O9)
DM388_BTMODE[10]: R24.2 R32.1 U7.R6(GPMC_D[10]/BTMODE[10]) U13.28(I/O10)
DM388_BTMODE[11]: R60.2 R101.1 U7.R4(GPMC_D[11]/BTMODE[11]) U13.33(I/O11)
DM388_BTMODE[12]: R29.2 U7.R3(GPMC_D[12]/BTMODE[12]) U13.40(I/O12)
DM388_BTMODE[13]: R45.2 R51.1 U7.R2(GPMC_D[13]/BTMODE[13]) U13.45(I/O13)
DM388_BTMODE[14]: R26.2 R34.1 U7.R1(GPMC_D[14]/BTMODE[14]) U13.46(I/O14)
DM388_BTMODE[15]: R22.2 R30.1 U7.P2(GPMC_D[15]/BTMODE[15]) U13.47(I/O15)
DM388_DDR0_A0: RA7.8 U6.N3(A0) U7.AL24(DDR[0]_A[0]) U8.N3(A0)
DM388_DDR0_A1: RA4.7 U6.P7(A1) U7.AC22(DDR[0]_A[1]) U8.P7(A1)
DM388_DDR0_A2: RA7.7 U6.P3(A2) U7.AJ23(DDR[0]_A[2]) U8.P3(A2)
DM388_DDR0_A3: RA8.6 U6.N2(A3) U7.AJ27(DDR[0]_A[3]) U8.N2(A3)
DM388_DDR0_A4: RA11.5 U6.P8(A4) U7.AK28(DDR[0]_A[4]) U8.P8(A4)
DM388_DDR0_A5: RA8.7 U6.P2(A5) U7.AH27(DDR[0]_A[5]) U8.P2(A5)
DM388_DDR0_A6: RA11.8 U6.R8(A6) U7.AK30(DDR[0]_A[6]) U8.R8(A6)
DM388_DDR0_A7: RA8.8 U6.R2(A7) U7.AG23(DDR[0]_A[7]) U8.R2(A7)
DM388_DDR0_A8: RA4.5 U6.T8(A8) U7.AL29(DDR[0]_A[8]) U8.T8(A8)
DM388_DDR0_A9: RA7.6 U6.R3(A9) U7.AK29(DDR[0]_A[9]) U8.R3(A9)
DM388_DDR0_A10: RA10.8 U6.L7(A10/AP) U7.AD23(DDR[0]_A[10]) U8.L7(A10/AP)
DM388_DDR0_A11: RA4.6 U6.R7(A11) U7.AK24(DDR[0]_A[11]) U8.R7(A11)
DM388_DDR0_A12: RA4.8 U6.N7(A12/~{BC}) U7.AH23(DDR[0]_A[12]) U8.N7(A12/~{BC})
DM388_DDR0_A13: RA7.5 U6.T3(A13) U7.AK23(DDR[0]_A[13]) U8.T3(A13)
DM388_DDR0_A14: RA11.6 U6.T7(A14) U7.AL23(DDR[0]_A[14]) U8.T7(A14)
DM388_DDR0_BA0: RA8.5 U6.M2(BA0) U7.AK26(DDR[0]_BA[0]) U8.M2(BA0)
DM388_DDR0_BA1: RA11.7 U6.N8(BA1) U7.AF23(DDR[0]_BA[1]) U8.N8(BA1)
DM388_DDR0_BA2: RA10.5 U6.M3(BA2) U7.AH25(DDR[0]_BA[2]) U8.M3(BA2)
DM388_DDR0_CASn: RA6.7 U6.K3(~{CAS}) U7.AK25(DDR[0]_CASn) U8.K3(~{CAS})
DM388_DDR0_CKE: RA10.7 U6.K9(CKE) U7.AD20(DDR[0]_CKE) U8.K9(CKE)
DM388_DDR0_CLK: R107.1 U6.J7(CK) U7.AL27(DDR[0]_CLK) U8.J7(CK)
DM388_DDR0_CLKn: R108.1 U6.K7(~{CK}) U7.AK27(DDR[0]_CLKn) U8.K7(~{CK})
DM388_DDR0_CS0n: RA6.8 U6.L2(~{CS}) U7.AB21(DDR[0]_CS[0]n) U8.L2(~{CS})
DM388_DDR0_DQ0: U6.E3(DQ0) U7.AL9(DDR[0]_D[0])
DM388_DDR0_DQ1: U6.F7(DQ1) U7.AK9(DDR[0]_D[1])
DM388_DDR0_DQ2: U6.F2(DQ2) U7.AK10(DDR[0]_D[2])
DM388_DDR0_DQ3: U6.F8(DQ3) U7.AJ11(DDR[0]_D[3])
DM388_DDR0_DQ4: U6.H3(DQ4) U7.AH11(DDR[0]_D[4])
DM388_DDR0_DQ5: U6.H8(DQ5) U7.AD9(DDR[0]_D[5])
DM388_DDR0_DQ6: U6.G2(DQ6) U7.AF11(DDR[0]_D[6])
DM388_DDR0_DQ7: U6.H7(DQ7) U7.AL12(DDR[0]_D[7])
DM388_DDR0_DQ8: U6.D7(DQ8) U7.AJ12(DDR[0]_D[8])
DM388_DDR0_DQ9: U6.C3(DQ9) U7.AG12(DDR[0]_D[9])
DM388_DDR0_DQ10: U6.C8(DQ10) U7.AD12(DDR[0]_D[10])
DM388_DDR0_DQ11: U6.C2(DQ11) U7.AB12(DDR[0]_D[11])
DM388_DDR0_DQ12: U6.A7(DQ12) U7.AK13(DDR[0]_D[12])
DM388_DDR0_DQ13: U6.A2(DQ13) U7.AC13(DDR[0]_D[13])
DM388_DDR0_DQ14: U6.B8(DQ14) U7.AL14(DDR[0]_D[14])
DM388_DDR0_DQ15: U6.A3(DQ15) U7.AK14(DDR[0]_D[15])
DM388_DDR0_DQ16: U7.AH15(DDR[0]_D[16]) U8.E3(DQ0)
DM388_DDR0_DQ17: U7.AF15(DDR[0]_D[17]) U8.F7(DQ1)
DM388_DDR0_DQ18: U7.AD15(DDR[0]_D[18]) U8.F2(DQ2)
DM388_DDR0_DQ19: U7.AK16(DDR[0]_D[19]) U8.F8(DQ3)
DM388_DDR0_DQ20: U7.AJ16(DDR[0]_D[20]) U8.H3(DQ4)
DM388_DDR0_DQ21: U7.AG16(DDR[0]_D[21]) U8.H8(DQ5)
DM388_DDR0_DQ22: U7.AD16(DDR[0]_D[22]) U8.G2(DQ6)
DM388_DDR0_DQ23: U7.AC16(DDR[0]_D[23]) U8.H7(DQ7)
DM388_DDR0_DQ24: U7.AK19(DDR[0]_D[24]) U8.D7(DQ8)
DM388_DDR0_DQ25: U7.AJ19(DDR[0]_D[25]) U8.C3(DQ9)
DM388_DDR0_DQ26: U7.AH19(DDR[0]_D[26]) U8.C8(DQ10)
DM388_DDR0_DQ27: U7.AF19(DDR[0]_D[27]) U8.C2(DQ11)
DM388_DDR0_DQ28: U7.AD19(DDR[0]_D[28]) U8.A7(DQ12)
DM388_DDR0_DQ29: U7.AC19(DDR[0]_D[29]) U8.A2(DQ13)
DM388_DDR0_DQ30: U7.AJ20(DDR[0]_D[30]) U8.B8(DQ14)
DM388_DDR0_DQ31: U7.AG20(DDR[0]_D[31]) U8.A3(DQ15)
DM388_DDR0_DQM0: U6.E7(LDM) U7.AL8(DDR[0]_DQM[0])
DM388_DDR0_DQM1: U6.D3(UDM) U7.AK12(DDR[0]_DQM[1])
DM388_DDR0_DQM2: U7.AJ15(DDR[0]_DQM[2]) U8.E7(LDM)
DM388_DDR0_DQM3: U7.AK18(DDR[0]_DQM[3]) U8.D3(UDM)
DM388_DDR0_DQS0: U6.F3(LDQS) U7.AL11(DDR[0]_DQS[0])
DM388_DDR0_DQS0n: U6.G3(~{LDQS}) U7.AK11(DDR[0]_DQS[0]n)
DM388_DDR0_DQS1: U6.C7(UDQS) U7.AL15(DDR[0]_DQS[1])
DM388_DDR0_DQS1n: U6.B7(~{UDQS}) U7.AK15(DDR[0]_DQS[1]n)
DM388_DDR0_DQS2: U7.AL17(DDR[0]_DQS[2]) U8.F3(LDQS)
DM388_DDR0_DQS2n: U7.AK17(DDR[0]_DQS[2]n) U8.G3(~{LDQS})
DM388_DDR0_DQS3: U7.AL20(DDR[0]_DQS[3]) U8.C7(UDQS)
DM388_DDR0_DQS3n: U7.AK20(DDR[0]_DQS[3]n) U8.B7(~{UDQS})
DM388_DDR0_ODT0: RA6.5 U6.K1(ODT) U7.AL21(DDR[0]_ODT[0]) U8.K1(ODT)
DM388_DDR0_RASn: RA6.6 U6.J3(~{RAS}) U7.AJ25(DDR[0]_RASn) U8.J3(~{RAS})
DM388_DDR0_RST: R72.2 U6.T2(~{RESET}) U7.AA20(DDR[0]_RST) U8.T2(~{RESET})
DM388_DDR0_VTP: R122.1 U7.AL30(DDR[0]_VTP)
DM388_DDR0_WEn: RA10.6 U6.L3(~{WE}) U7.AL26(DDR[0]_WEn) U8.L3(~{WE})
DM388_GP1[14]: U7.M5(GPMC_A[19]/TIM3_IO/GP1[14]) ; also on sheet 21
DM388_GP1[24]: U7.AA12(GPMC_CS[1]n/GPMC_A[25]/GP1[24]) ; also on sheet 21
DM388_GP1[25]: U7.AC3(GPMC_CS[2]n/GPMC_A[24]/GP1[25]) ; also on sheet 21
DM388_GP1[30]: U7.Y11(GPMC_BE[1]n/GPMC_A[24]/EDMA_EVT1/TIM7_IO/GP1[30]) ; also on sheet 21
DM388_GPMC_ALE: U7.AA10(GPMC_ADVn_ALE/GPMC_CS[6]n/TIM5_IO/GP1[28]) U13.17(ALE)
DM388_GPMC_CLE: U7.Y3(GPMC_BE[0]n_CLE/GPMC_A[25]/EDMA_EVT2/TIM6_IO/GP1[29]) U13.16(CLE)
DM388_GPMC_CS[0]n: U7.AC9(GPMC_CS[0]n/GP1[23]) U13.9(~{CE})
DM388_GPMC_OEn_REn: U7.Y8(GPMC_OEn_REn) U13.8(~{RE})
DM388_GPMC_WAIT0: R20.2 U7.W8(GPMC_WAIT[0]/GPMC_A[26]/EDMA_EVT0/GP1[31]) U13.7(R/~{B})
DM388_GPMC_WEn: U7.Y5(GPMC_WEn) U13.18(~{WE})
DM388_GPMC_WPn: R35.2 U7.AF2(GPMC_CS[3]n/VIN[1]B_CLK/SPI[2]_SCS[0]n/GP1[26]) U13.19(~{WP})
DM388_HDMI_CEC: U7.N2(GPMC_A[22]/SPI[2]_D[1]/HDMI_CEC/TIM4_IO/GP1[17]) ; also on sheet 21
DM388_HDMI_HPDET: U7.R8(GPMC_A[23]/SPI[2]_SCLK/HDMI_HPDET/TIM5_IO/GP1[18]) ; also on sheet 21
DM388_MUX_SEL: U7.N1(GPMC_A[21]/SPI[2]_D[0]/GP1[16]) ; also on sheet 12
DM388_PORn: R83.1 U7.AH30(PORn) U11.4(Y)
DM388_RSTOUT: R81.1 U7.AJ30(RSTOUTn_WD_OUTn) ; also on sheet 21
DM388_TPS_SLEEP: U7.N9(GPMC_A[20]/SPI[2]_SCS[1]n/GP1[15]) ; also on sheet 17
DM388_WARM_RSTn: R131.2 U7.AH29(RESETn) ; also on sheet 21
DM388_WLAN_CLKOUT1: R116.1 ; also on sheet 12
DM388_WLAN_EN: U7.M2(GPMC_A[17]/GP2[6]) ; also on sheet 12
DM388_WLAN_IRQ: U7.M3(GPMC_A[18]/TIM2_IO/GP1[13]) ; also on sheet 12
nRESPWRON2: U11.1(A) ; also on sheet 17
OSC_WAKE: U7.U28(DEVOSC_WAKE/SPI[1]_SCS[1]n/TIM5_IO/GP1[7]) ; also on sheet 21
TPS_INT1: U7.AH31(NMIn) ; also on sheet 17 21
XTAL_GND1: C59.1 C62.1 U7.G30(VSSA_DEVOSC) Y2.2 Y2.4
XTAL_GND2: C60.1 C61.2 U7.U30(VSSA_AUXOSC) Y3.2 Y3.4
N11812612: C98.2 R107.2 R108.2
N12895522: C62.2 U7.G31(DEVOSC_MXO) Y2.3
N12895682: C61.1 U7.V30(AUXOSC_MXI) Y3.3
N12895686: C60.2 U7.U31(AUXOSC_MXO) Y3.1
N12985066: R85.2 U10.1(EOH)
N12985136: R82.1 U10.3(OUTPUT)
N12993482: R132.2 U8.L8(ZQ)
N14553661: R116.2 U7.AB9(GPMC_CLK/GPMC_CS[5]n/GPMC_WAIT[1]/CLKOUT1/EDMA_EVT3/TIM4_IO/GP1[27])
N14634458: R59.2 SW1.1
N14648093: C59.2 U7.F30(DEVOSC_MXI/DEV_CLKIN) Y2.1
N15140205: R119.2 U6.L8(ZQ)

Not connected (* = marked no-connect by the designer): U6 J1(NC1)* J9(NC2)* L1(NC3)* L9(NC4)* M7(NC5)*; U7 AK21(RSV42)* AK22(DDR[0]_A[15])*; U8 J1(NC1)* J9(NC2)* L1(NC3)* L9(NC4)* M7(NC5)*; U13 1(NC-1)* 2(NC-2)* 3(NC-3)* 4(NC-4)* 5(NC-5)* 6(NC-6)* 10(NC-7)* 11(NC-8)* 14(NC-9)* 15(NC-10)* 20(NC-11)* 21(NC-12)* 22(NC-13)* 23(NC-14)* 24(NC-15)* 35(NC-16)* 38(DNU)*

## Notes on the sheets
sheet 1
- HARDWARE SCHEMATICS
- FIDUCIALS
- MicroSD CARD
- LOGOs & LABELs
- Serial No:
- ASSY REV
sheet 2
- POWER CALCULATION
sheet 3
- POWER UP SEQUENCE
sheet 4
- GPIO TABLE
- I2C ADDRESS TABLE
- Internal/
  External
  PU/PD states
- MASTER
- I2C
  USED
- SLAVE DEVICE
- ADDRESS
- GPIO NAME
- PROCESSOR PIN
- PURPOSE
- NMIn interrupt from PMIC to
  DM388 processor
- INTERNAL PU
- I2C0
- PMIC
- 0x2D
  (General Purpose)
- TPS_INT1
- NMI
- EXTERNAL PU
- DM388_GPMC_WPn
- GP1[26]
- WRITE PROTECT TO NAND FLASH
- 0x10
  (Camera Sensor)
- DM388_WLAN_IRQ
- GP1[13]
- INTERRUPT FROM WL1837 MOD
- EXTERNAL PU
- DM388
  PROCESSOR
- Camera Module
- 0x2D
  (LVDS module)
- DM388_WLAN_EN
- GP2[6]
- WLAN ENABLE SIGNAL TO WIFI
  MODULE (WL1837)
- INTERNAL PD
- I2C2
- DM388_BT_EN
- GP2[5]
- BLUETOOTH ENABLE SIGNAL TO
  WIFI MODULE (WL1837)
- INTERNAL PD
- Audio Codec
  (TLV320AIC3104)
- 0x18
- DM388_TPS_SLEEP
- GP1[15]
- PMIC SLEEP INPUT
- INTERNAL PU
- DM388_MUX_SEL
- GP1[16]
- SELECTION SIGNAL TO CAMERA &
  UART MUXER
- EXTERNAL PD
- ENET_RSTn
- INTERNAL PU
- GP3[20]
- ETHERNET RESET
- DM388_MMC1_DAT6
  /GP0_12
- GP0[12]
- KEYPAD
- INTERNAL PU
- DM388_MMC1_DAT7
  /GP0_13
- GP0[13]
- KEYPAD
- INTERNAL PU
- DM388_GP1[10]
- GP1[10]
- INTERNAL PD
- KEYPAD
- DM388_McASP0_AXR5
- MCA[0]_AXR[5]
- KEYPAD
- INTERNAL PD
- DM388_GP3[3]
- GP3[3]
- LED
- INTERNAL PD
- DM388_GP0[9]
- GP0[9]
- INTERNAL PD
- LED
- DM388_GP1[24]
- GP1[24]
- INTERNAL PU
- LED
- DM388_GP1[25]
- GP1[25]
- LED
- INTERNAL PU
- DM388_GP1[30]
- GP1[30]
- LED
- INTERNAL PD
sheet 5
- TMDSCSK388
- TABLE OF CONTENTS
- REV
- REV B
- PAGE
- CONTENTS
- 01
- TABLE OF CONTENTS
- VER
- 3.0
- 02
- REVISION HISTORY
- 03
- BLOCK DIAGRAM
- 04
- POWER FLOW DIAGRAM
- 05
- POWER UP SEQUENCE
- 06
- POWER CALCULATION
- 07
- GPIO & I2C ADDRESS TABLE
- 08
- CLOCKS & RESET
- 09
- NAND FLASH,BOOTMODE & GPIOs
- 10
- DDR3 INTERFACE
- 11
- DM388 I/O PERIPHERALS
- 12
- WLAN TRANSLATORS & CAM MUXER
- 13
- WLAN + BT MODULE
- 14
- DM388 POWER
- 15
- DM388 VSS
- 16
- PMIC POWER 1
- 17
- PMIC POWER 2
- 18
- DDR3 POWER
- 19
- ETHERNET,HDMI & USB
- 20
- CAMERA,JTAG,CSI
- 21
- BOARD TO BOARD CONNECTORS
- 22
- HARDWARE SCHEMATICS
sheet 6
- REVISION HISTORY
- VER #
- DATE
- DESCRIPTION OF CHANGES
- AUTHOR
- REVIEWED  BY
- APPROVED  BY
- 0.1
- 22nd SEP 2016
- REVA Change List implemented
  Baselined for REVB
- Mistral Design Team
- AJIT MB
- AJIT MB
- 0.2
- 4th NOV 2016
- I2C0 SDA and I2C0 SCL lines to PMIC updated
- Mistral Design Team
- AJIT MB
- AJIT MB
- 1.0
- 8th NOV 2016
- Baselined
- Mistral Design Team
- AJIT MB
- AJIT MB
- 1.1
- 6th JAN 2017
- SD card Part#  added to  hardware schematics page
- Mistral Design Team
- AJIT MB
- AJIT MB
- 2.0
- 6th JAN 2017
- Baselined
- Mistral Design Team
- AJIT MB
- AJIT MB
- 2.1
- 13th JAN 2017
- Renamed the Schematics from PRDN_REVA to REV B
- Mistral Design Team
- AJIT MB
- AJIT MB
- 3.0
- 13th JAN 2017
- Baselined
- Mistral Design Team
- AJIT MB
- AJIT MB
sheet 7
- BLOCK DIAGRAM
sheet 8
- POWER FLOW DIAGRAM
- BOARD TO BOARD CONNECTORS X2
- EN_LS_3V3
- VCC_5V0
  +5.0V
- VBACK
  UP
- PMIC_3V3
  +3.3V
- VCC_3V3
  +3.3V
- PMIC  TPS6591133
- NAND FLASH
  MT29F2G16ABAEAWP:E
- EN_TPS51216
- LDO TPS71711DCKR
- DDR3 POWER TPS51216
- MUXER
  SN74CBTLV3257RGYR
- LEDs x1
- VDDR_VTT
  +0.75V
- VDD_DDR
  +1.5V
- VDD_DDR_VREF
  +0.75V
- 3 INPUT AND GATE
  SN74LVC1G11DCKR
- DDR3 x2
  MT41K256M16TW 107
- SHUNT REGULATOR
  TLV431ACDBVR
- Level Translator
  TXS0108ERGYR
- Level Translator x3
  SN74AVC4T245RGYR
- VDD_DDR
  +1.5V
- VDD_DDR_
  VREF
  +0.75V
- CVDD
  ARM
  +1.2V
- CVDD
  HDVICP
  +1.2V
- CORE
  CVDD
  +1.2V
- TPS VDDA
  1V8
  +1.8V
- VCC_3V3
  +3.3V
- TPS VHD
  1V1
  +1.1V
- HDDAC_
  VREF
  +0.5V
- WIFI+BT MODULE
  WL1837
- DM388 PROCESSOR
- NOTE:
- REGULATORS
- DEVICES
- Multiple powered
  device
sheet 9
- CLOCKS AND RESET
- TC25L5C32K7680
- ECS-200-CDX-0998
- ECS-200-CDX-0998
sheet 10
- NAND FLASH
- GPIOs
- BOOTMODE TABLE
- BOOTMODE
  PIN
- DEFAULT
  SETTING
- DESCRIPTION
- BOOT MODE
- BTMODE15
- 0
- GPMC CS0 Wait disabled
- BTMODE14
- 0
- GPMC CS0 Address/Data not
  muxed
- BTMODE13
- 0
- BTMODE12
- 1
- GPMC CS0 16bit Data bus
- RSTOUT is asserted when a
  Watchdog Timer reset, POR,
  RESET, or Emulation/
  Software-Global
  Cold/Warm reset occurs
- BTMODE11
- 0
- BTMODE10
- 0
- GPMC Option A
- BOOTMODE SELECTION
- BTMODE9
- 0
- MII (GMII) Ethernet PHY
  Mode
- BTMODE8
- 0
- SW1
- SELECTION
- RGMII Internal delay
  disabled
- BTMODE7
- 1
- ON
- MMC BOOT
- BTMODE6
- 0
- RSV
- OFF
- NAND
- BTMODE5
- 0
- RSV
- 10011
- NAND BOOT
- BTMODE[4:0]
- 10111
- MMC BOOT
sheet 11
- DM388 DDR INTERFACE
- DDR TERMINATION
- DDR DEVICE 2
- DDR DEVICE 1
